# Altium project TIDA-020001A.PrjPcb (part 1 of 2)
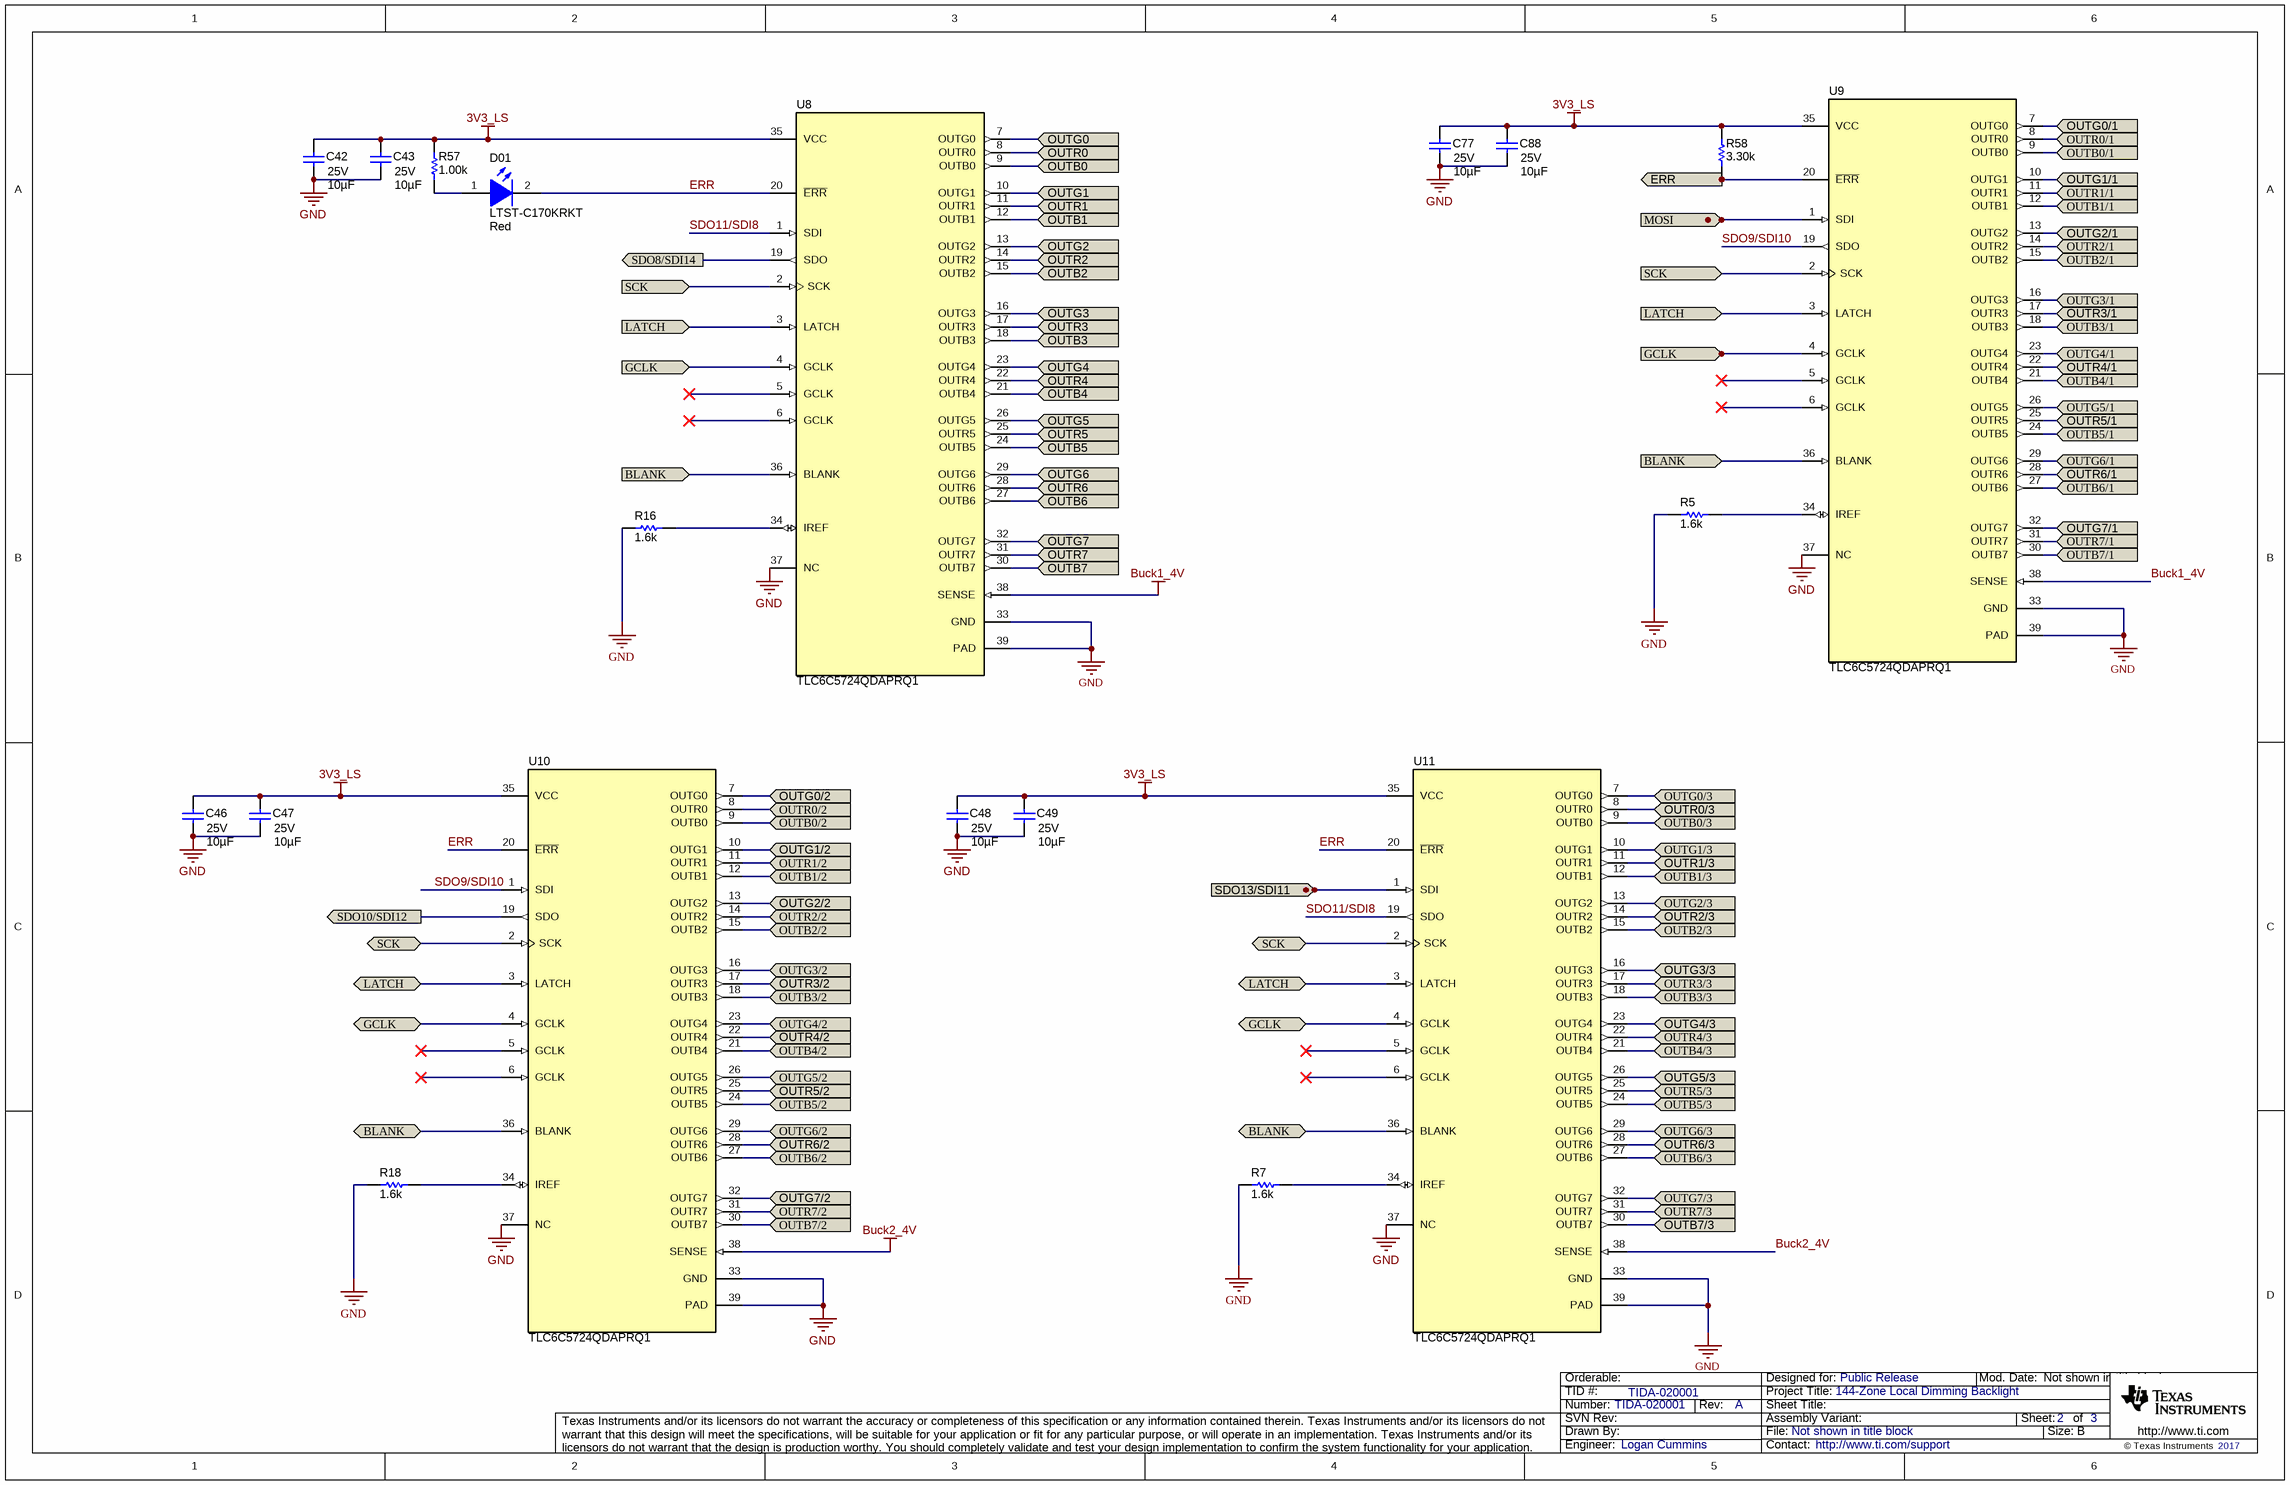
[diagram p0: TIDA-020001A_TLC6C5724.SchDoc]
TID: TIDA-020001; TechSupport: http://www.ti.com/support; SCH_Rev: A; PRJ_Title: 144-Zone Local Dimming Backlight; PRJ_Number: TIDA-020001; PRJ_Engineer: Logan Cummins; PRJ_Customer: Public Release; PCB_Rev: A; PCB_Layout: Logan Cummins; CopyrightYear: 2017
6 sheets, 284 parts. Net scope: global (net labels, ports and power ports of the same name join across sheets).
Board file: TIDA-020001A.PcbDoc
Sheets:
  TIDA-020001A_TLC6C5724.SchDoc
  TIDA-020001A_TLC6C5716.SchDoc
  TIDA-020001A_OPT&C2000.SchDoc
  TIDA-020001A_LEDs.SchDoc
  TIDA-020001A_LM74700&LMR14030.SchDoc
  TIDA-020001A_Hardware.SchDoc

## Sheet TIDA-020001A_TLC6C5724.SchDoc
size 431 x 279 mm; Date: Not shown in title block; ApprovedBy: Not shown in title block; CheckedBy: Not shown in title block; Author: Not shown in title block; CompanyName: Not shown in title block; Engineer: Not shown in title block; Organization: Not shown in title block; Address1: Not shown in title block; Address2: Not shown in title block; Address3: Not shown in title block; Address4: Not shown in title block; DocumentNumber: 1; Revision: Use project parameter SCH_Rev; SheetNumber: 2; SheetTotal: 3; PageSetup: Record=PageOptions¦CenterHorizontal=True¦CenterVertical=True¦PrintScale=1.00¦XCorrection=1.00¦YCorrection=1.00¦PrintKind=0¦BorderSize=5000000¦LeftOffset=0¦BottomOffset=0¦Orientation=2¦PaperLength=1000¦PaperWidth=1000¦Scale=100¦PaperSource=15¦PrintQuality=600¦MediaType=1¦DitherType=10¦PaperKind=Letter¦PrintScaleMode=1

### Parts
C42  ValueDisplayed: 10µF  Value2: 25V  [0603]  (hidden comment: GRM188R61E106MA73D)
C43  ValueDisplayed: 10µF  Value2: 25V  [0603]  (hidden comment: GRM188R61E106MA73D)
C46  ValueDisplayed: 10µF  Value2: 25V  [0603]  (hidden comment: GRM188R61E106MA73D)
C47  ValueDisplayed: 10µF  Value2: 25V  [0603]  (hidden comment: GRM188R61E106MA73D)
C48  ValueDisplayed: 10µF  Value2: 25V  [0603]  (hidden comment: GRM188R61E106MA73D)
C49  ValueDisplayed: 10µF  Value2: 25V  [0603]  (hidden comment: GRM188R61E106MA73D)
C77  ValueDisplayed: 10µF  Value2: 25V  [0603]  (hidden comment: GRM188R61E106MA73D)
C88  ValueDisplayed: 10µF  Value2: 25V  [0603]  (hidden comment: GRM188R61E106MA73D)
D01  LTST-C170KRKT  value Red  [LED_LTST-C170_Red]
R5  ValueDisplayed: 1.6k  [0603]  (hidden comment: CRCW06031K60JNEA)
R7  ValueDisplayed: 1.6k  [0603]  (hidden comment: CRCW06031K60JNEA)
R16  ValueDisplayed: 1.6k  [0603]  (hidden comment: CRCW06031K60JNEA)
R18  ValueDisplayed: 1.6k  [0603]  (hidden comment: CRCW06031K60JNEA)
R57  ValueDisplayed: 1.00k  [0603]  (hidden comment: RNCF0603TKY1K00)
R58  ValueDisplayed: 3.30k  [0603]  (hidden comment: RC0603FR-073K3L)
U8  TLC6C5724QDAPRQ1  [DAP0038E]
U9  TLC6C5724QDAPRQ1  [DAP0038E]
U10  TLC6C5724QDAPRQ1  [DAP0038E]
U11  TLC6C5724QDAPRQ1  [DAP0038E]

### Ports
BLANK, ERR, GCLK, LATCH, MOSI, OUTB0, OUTB0/1, OUTB0/2, OUTB0/3, OUTB1, OUTB1/1, OUTB1/2, OUTB1/3, OUTB2, OUTB2/1, OUTB2/2, OUTB2/3, OUTB3, OUTB3/1, OUTB3/2, OUTB3/3, OUTB4, OUTB4/1, OUTB4/2, OUTB4/3, OUTB5, OUTB5/1, OUTB5/2, OUTB5/3, OUTB6, OUTB6/1, OUTB6/2, OUTB6/3, OUTB7, OUTB7/1, OUTB7/2, OUTB7/3, OUTG0, OUTG0/1, OUTG0/2, OUTG0/3, OUTG1, OUTG1/1, OUTG1/2, OUTG1/3, OUTG2, OUTG2/1, OUTG2/2, OUTG2/3, OUTG3, OUTG3/1, OUTG3/2, OUTG3/3, OUTG4, OUTG4/1, OUTG4/2, OUTG4/3, OUTG5, OUTG5/1, OUTG5/2, OUTG5/3, OUTG6, OUTG6/1, OUTG6/2, OUTG6/3, OUTG7, OUTG7/1, OUTG7/2, OUTG7/3, OUTR0, OUTR0/1, OUTR0/2, OUTR0/3, OUTR1, OUTR1/1, OUTR1/2, OUTR1/3, OUTR2, OUTR2/1, OUTR2/2, OUTR2/3, OUTR3, OUTR3/1, OUTR3/2, OUTR3/3, OUTR4, OUTR4/1, OUTR4/2, OUTR4/3, OUTR5, OUTR5/1, OUTR5/2, OUTR5/3, OUTR6, OUTR6/1, OUTR6/2, OUTR6/3, OUTR7, OUTR7/1, OUTR7/2, OUTR7/3, SCK, SDO8/SDI14, SDO10/SDI12, SDO13/SDI11

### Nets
3V3_LS: C42.1 C43.1 C46.1 C47.1 C48.1 C49.1 C77.1 C88.1 R57.2 R58.2 U8.35(VCC) U9.35(VCC) U10.35(VCC) U11.35(VCC)
Buck1_4V: U8.38(SENSE) U9.38(SENSE)
Buck2_4V: U10.38(SENSE) U11.38(SENSE)
GND: C42.2 C43.2 C46.2 C47.2 C48.2 C49.2 C77.2 C88.2 R5.1 R7.1 R16.1 R18.1 U8.33(GND) U8.37(NC) U8.39(PAD) U9.33(GND) U9.37(NC) U9.39(PAD) U10.33(GND) U10.37(NC) U10.39(PAD) U11.33(GND) U11.37(NC) U11.39(PAD)
BLANK: U8.36(BLANK) U9.36(BLANK) U10.36(BLANK) U11.36(BLANK) ; port BLANK
ERR: D01.2(K) R58.1 U8.20(~{ERR}) U9.20(~{ERR}) U10.20(~{ERR}) U11.20(~{ERR}) ; port ERR
GCLK: U8.4(GCLK) U9.4(GCLK) U10.4(GCLK) U11.4(GCLK) ; port GCLK
LATCH: U8.3(LATCH) U9.3(LATCH) U10.3(LATCH) U11.3(LATCH) ; port LATCH
MOSI: U9.1(SDI) ; port MOSI
OUTB0: U8.9(OUTB0) ; port OUTB0
OUTB0/1: U9.9(OUTB0) ; port OUTB0/1
OUTB0/2: U10.9(OUTB0) ; port OUTB0/2
OUTB0/3: U11.9(OUTB0) ; port OUTB0/3
OUTB1: U8.12(OUTB1) ; port OUTB1
OUTB1/1: U9.12(OUTB1) ; port OUTB1/1
OUTB1/2: U10.12(OUTB1) ; port OUTB1/2
OUTB1/3: U11.12(OUTB1) ; port OUTB1/3
OUTB2: U8.15(OUTB2) ; port OUTB2
OUTB2/1: U9.15(OUTB2) ; port OUTB2/1
OUTB2/2: U10.15(OUTB2) ; port OUTB2/2
OUTB2/3: U11.15(OUTB2) ; port OUTB2/3
OUTB3: U8.18(OUTB3) ; port OUTB3
OUTB3/1: U9.18(OUTB3) ; port OUTB3/1
OUTB3/2: U10.18(OUTB3) ; port OUTB3/2
OUTB3/3: U11.18(OUTB3) ; port OUTB3/3
OUTB4: U8.21(OUTB4) ; port OUTB4
OUTB4/1: U9.21(OUTB4) ; port OUTB4/1
OUTB4/2: U10.21(OUTB4) ; port OUTB4/2
OUTB4/3: U11.21(OUTB4) ; port OUTB4/3
OUTB5: U8.24(OUTB5) ; port OUTB5
OUTB5/1: U9.24(OUTB5) ; port OUTB5/1
OUTB5/2: U10.24(OUTB5) ; port OUTB5/2
OUTB5/3: U11.24(OUTB5) ; port OUTB5/3
OUTB6: U8.27(OUTB6) ; port OUTB6
OUTB6/1: U9.27(OUTB6) ; port OUTB6/1
OUTB6/2: U10.27(OUTB6) ; port OUTB6/2
OUTB6/3: U11.27(OUTB6) ; port OUTB6/3
OUTB7: U8.30(OUTB7) ; port OUTB7
OUTB7/1: U9.30(OUTB7) ; port OUTB7/1
OUTB7/2: U10.30(OUTB7) ; port OUTB7/2
OUTB7/3: U11.30(OUTB7) ; port OUTB7/3
OUTG0: U8.7(OUTG0) ; port OUTG0
OUTG0/1: U9.7(OUTG0) ; port OUTG0/1
OUTG0/2: U10.7(OUTG0) ; port OUTG0/2
OUTG0/3: U11.7(OUTG0) ; port OUTG0/3
OUTG1: U8.10(OUTG1) ; port OUTG1
OUTG1/1: U9.10(OUTG1) ; port OUTG1/1
OUTG1/2: U10.10(OUTG1) ; port OUTG1/2
OUTG1/3: U11.10(OUTG1) ; port OUTG1/3
OUTG2: U8.13(OUTG2) ; port OUTG2
OUTG2/1: U9.13(OUTG2) ; port OUTG2/1
OUTG2/2: U10.13(OUTG2) ; port OUTG2/2
OUTG2/3: U11.13(OUTG2) ; port OUTG2/3
OUTG3: U8.16(OUTG3) ; port OUTG3
OUTG3/1: U9.16(OUTG3) ; port OUTG3/1
OUTG3/2: U10.16(OUTG3) ; port OUTG3/2
OUTG3/3: U11.16(OUTG3) ; port OUTG3/3
OUTG4: U8.23(OUTG4) ; port OUTG4
OUTG4/1: U9.23(OUTG4) ; port OUTG4/1
OUTG4/2: U10.23(OUTG4) ; port OUTG4/2
OUTG4/3: U11.23(OUTG4) ; port OUTG4/3
OUTG5: U8.26(OUTG5) ; port OUTG5
OUTG5/1: U9.26(OUTG5) ; port OUTG5/1
OUTG5/2: U10.26(OUTG5) ; port OUTG5/2
OUTG5/3: U11.26(OUTG5) ; port OUTG5/3
OUTG6: U8.29(OUTG6) ; port OUTG6
OUTG6/1: U9.29(OUTG6) ; port OUTG6/1
OUTG6/2: U10.29(OUTG6) ; port OUTG6/2
OUTG6/3: U11.29(OUTG6) ; port OUTG6/3
OUTG7: U8.32(OUTG7) ; port OUTG7
OUTG7/1: U9.32(OUTG7) ; port OUTG7/1
OUTG7/2: U10.32(OUTG7) ; port OUTG7/2
OUTG7/3: U11.32(OUTG7) ; port OUTG7/3
OUTR0: U8.8(OUTR0) ; port OUTR0
OUTR0/1: U9.8(OUTR0) ; port OUTR0/1
OUTR0/2: U10.8(OUTR0) ; port OUTR0/2
OUTR0/3: U11.8(OUTR0) ; port OUTR0/3
OUTR1: U8.11(OUTR1) ; port OUTR1
OUTR1/1: U9.11(OUTR1) ; port OUTR1/1
OUTR1/2: U10.11(OUTR1) ; port OUTR1/2
OUTR1/3: U11.11(OUTR1) ; port OUTR1/3
OUTR2: U8.14(OUTR2) ; port OUTR2
OUTR2/1: U9.14(OUTR2) ; port OUTR2/1
OUTR2/2: U10.14(OUTR2) ; port OUTR2/2
OUTR2/3: U11.14(OUTR2) ; port OUTR2/3
OUTR3: U8.17(OUTR3) ; port OUTR3
OUTR3/1: U9.17(OUTR3) ; port OUTR3/1
OUTR3/2: U10.17(OUTR3) ; port OUTR3/2
OUTR3/3: U11.17(OUTR3) ; port OUTR3/3
OUTR4: U8.22(OUTR4) ; port OUTR4
OUTR4/1: U9.22(OUTR4) ; port OUTR4/1
OUTR4/2: U10.22(OUTR4) ; port OUTR4/2
OUTR4/3: U11.22(OUTR4) ; port OUTR4/3
OUTR5: U8.25(OUTR5) ; port OUTR5
OUTR5/1: U9.25(OUTR5) ; port OUTR5/1
OUTR5/2: U10.25(OUTR5) ; port OUTR5/2
OUTR5/3: U11.25(OUTR5) ; port OUTR5/3
OUTR6: U8.28(OUTR6) ; port OUTR6
OUTR6/1: U9.28(OUTR6) ; port OUTR6/1
OUTR6/2: U10.28(OUTR6) ; port OUTR6/2
OUTR6/3: U11.28(OUTR6) ; port OUTR6/3
OUTR7: U8.31(OUTR7) ; port OUTR7
OUTR7/1: U9.31(OUTR7) ; port OUTR7/1
OUTR7/2: U10.31(OUTR7) ; port OUTR7/2
OUTR7/3: U11.31(OUTR7) ; port OUTR7/3
SCK: U8.2(SCK) U9.2(SCK) U10.2(SCK) U11.2(SCK) ; port SCK
SDO8/SDI14: U8.19(SDO) ; port SDO8/SDI14
SDO9/SDI10: U9.19(SDO) U10.1(SDI)
SDO10/SDI12: U10.19(SDO) ; port SDO10/SDI12
SDO11/SDI8: U8.1(SDI) U11.19(SDO)
SDO13/SDI11: U11.1(SDI) ; port SDO13/SDI11
NetD01_1: D01.1(A) R57.1
NetR5_2: R5.2 U9.34(IREF)
NetR7_2: R7.2 U11.34(IREF)
NetR16_2: R16.2 U8.34(IREF)
NetR18_2: R18.2 U10.34(IREF)

Not connected (* = marked no-connect by the designer): U8 5(GCLK)* 6(GCLK)*; U9 5(GCLK)* 6(GCLK)*; U10 5(GCLK)* 6(GCLK)*; U11 5(GCLK)* 6(GCLK)*

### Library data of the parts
C42 C43 C46-C49 C77 C88 = GRM188R61E106MA73D: CAP, CERM, 10 µF, 25 V, +/- 20%, X5R, 0603; Manufacturer: MuRata; Polarized: N; CompType: Capacitor; Value: 10uF; U/M: EA; Cap_F: 0.00001; Tolerance_%: 20; Value1: Unknown; VDC_V: 25; TaMin_C: -55; TaMax_C: 85; SizeArea_mm2: 1.28; SizeAreaWB_mm2: 4.68; SizeX_mm: 1.6; SizeY_mm: 0.8; SizeZ_mm: 1; AEC Category: Q200
D01 = CMP-0002829-2: LED, Red, SMD; Manufacturer: Lite-On; Io_A: 20mA; SizeAreaWB_mm2: 6.75; Value1: W; U/M: EA; SizeZ_mm: 1.2; SizeX_mm: 2; SizeY_mm: 1.25; Vf_V: 2V; SizeArea_mm2: 2.5; Type: AlInGaP
R5 R7 R16 R18 = CRCW06031K60JNEA: RES, 1.6 k, 5%, 0.1 W, 0603; Manufacturer: Vishay-Dale; CompType: Resistor; Value: 1.6k; Res_ohm: 1600; Value_Code: 1k60; Tolerance_%: 5; Power_W: 0.1; Value2: 0.1W; VDC_V: 75; TempCo: 200 ppm/C; SizeArea_mm2: 1.28; SizeX_mm: 1.6; SizeY_mm: 0.8; SizeZ_mm: 1; EIA_Code: E24; U/M: EA; AEC Category: Q200
R57 = RNCF0603TKY1K00: RES, 1.00 k, 0.01%, 0.063 W, 0603; Manufacturer: Stackpole Electronics Inc; CompType: Resistor; Value: 1.00k; Res_ohm: 1000; Value_Code: 1k00; Tolerance_%: 0.01; Power_W: 0.063; Value2: 0.063W; VDC_V: 50; TempCo: 5 ppm/C; SizeArea_mm2: 1.28; SizeX_mm: 1.6; SizeY_mm: 0.8; SizeZ_mm: 1; U/M: EA; AEC Category: Q200; Green_Lifecycle: Active; Green_REACh: Passed
R58 = RC0603FR-073K3L: RES, 3.30 k, 1%, 0.1 W, 0603; Manufacturer: Yageo America; CompType: Resistor; Value: 3.30k; Res_ohm: 3300; Value_Code: 3k30; Tolerance_%: 1; Power_W: 0.1; Value2: 0.1W; VDC_V: 150; TempCo: 200 ppm/C; SizeArea_mm2: 1.28; SizeX_mm: 1.6; SizeY_mm: 0.8; U/M: EA; AEC Category: Q200; Green_Lifecycle: Active; Green_REACh: Passed
U8-U11 = TLC6C5724QDAPRQ1: 24-Channel, Full Diagnostics, Constant-Current LED Driver with 7-Bit Dot Correction and 12-Bit PWM Dimming, DAP0038E (TSSOP-38); Manufacturer: Texas Instruments; SymbolCreator: Altium; SizeArea_mm2: 101.25; SizeAreaWB_mm2: 146.45; SizeX_mm: 8.1; SizeY_mm: 12.5; SizeZ_mm: 1.2; CompType: IC; U/M: EA

## Sheet TIDA-020001A_TLC6C5716.SchDoc
size 431 x 279 mm; Date: Not shown in title block; ApprovedBy: Not shown in title block; CheckedBy: Not shown in title block; Author: Not shown in title block; CompanyName: Not shown in title block; Engineer: Not shown in title block; Organization: Not shown in title block; Address1: Not shown in title block; Address2: Not shown in title block; Address3: Not shown in title block; Address4: Not shown in title block; DocumentNumber: 1; Revision: Use project parameter SCH_Rev; SheetNumber: 2; SheetTotal: 3; PageSetup: Record=PageOptions¦CenterHorizontal=True¦CenterVertical=True¦PrintScale=1.00¦XCorrection=1.00¦YCorrection=1.00¦PrintKind=0¦BorderSize=5000000¦LeftOffset=0¦BottomOffset=0¦Orientation=2¦PaperLength=1000¦PaperWidth=1000¦Scale=100¦PaperSource=15¦PrintQuality=600¦MediaType=1¦DitherType=10¦PaperKind=Letter¦PrintScaleMode=1
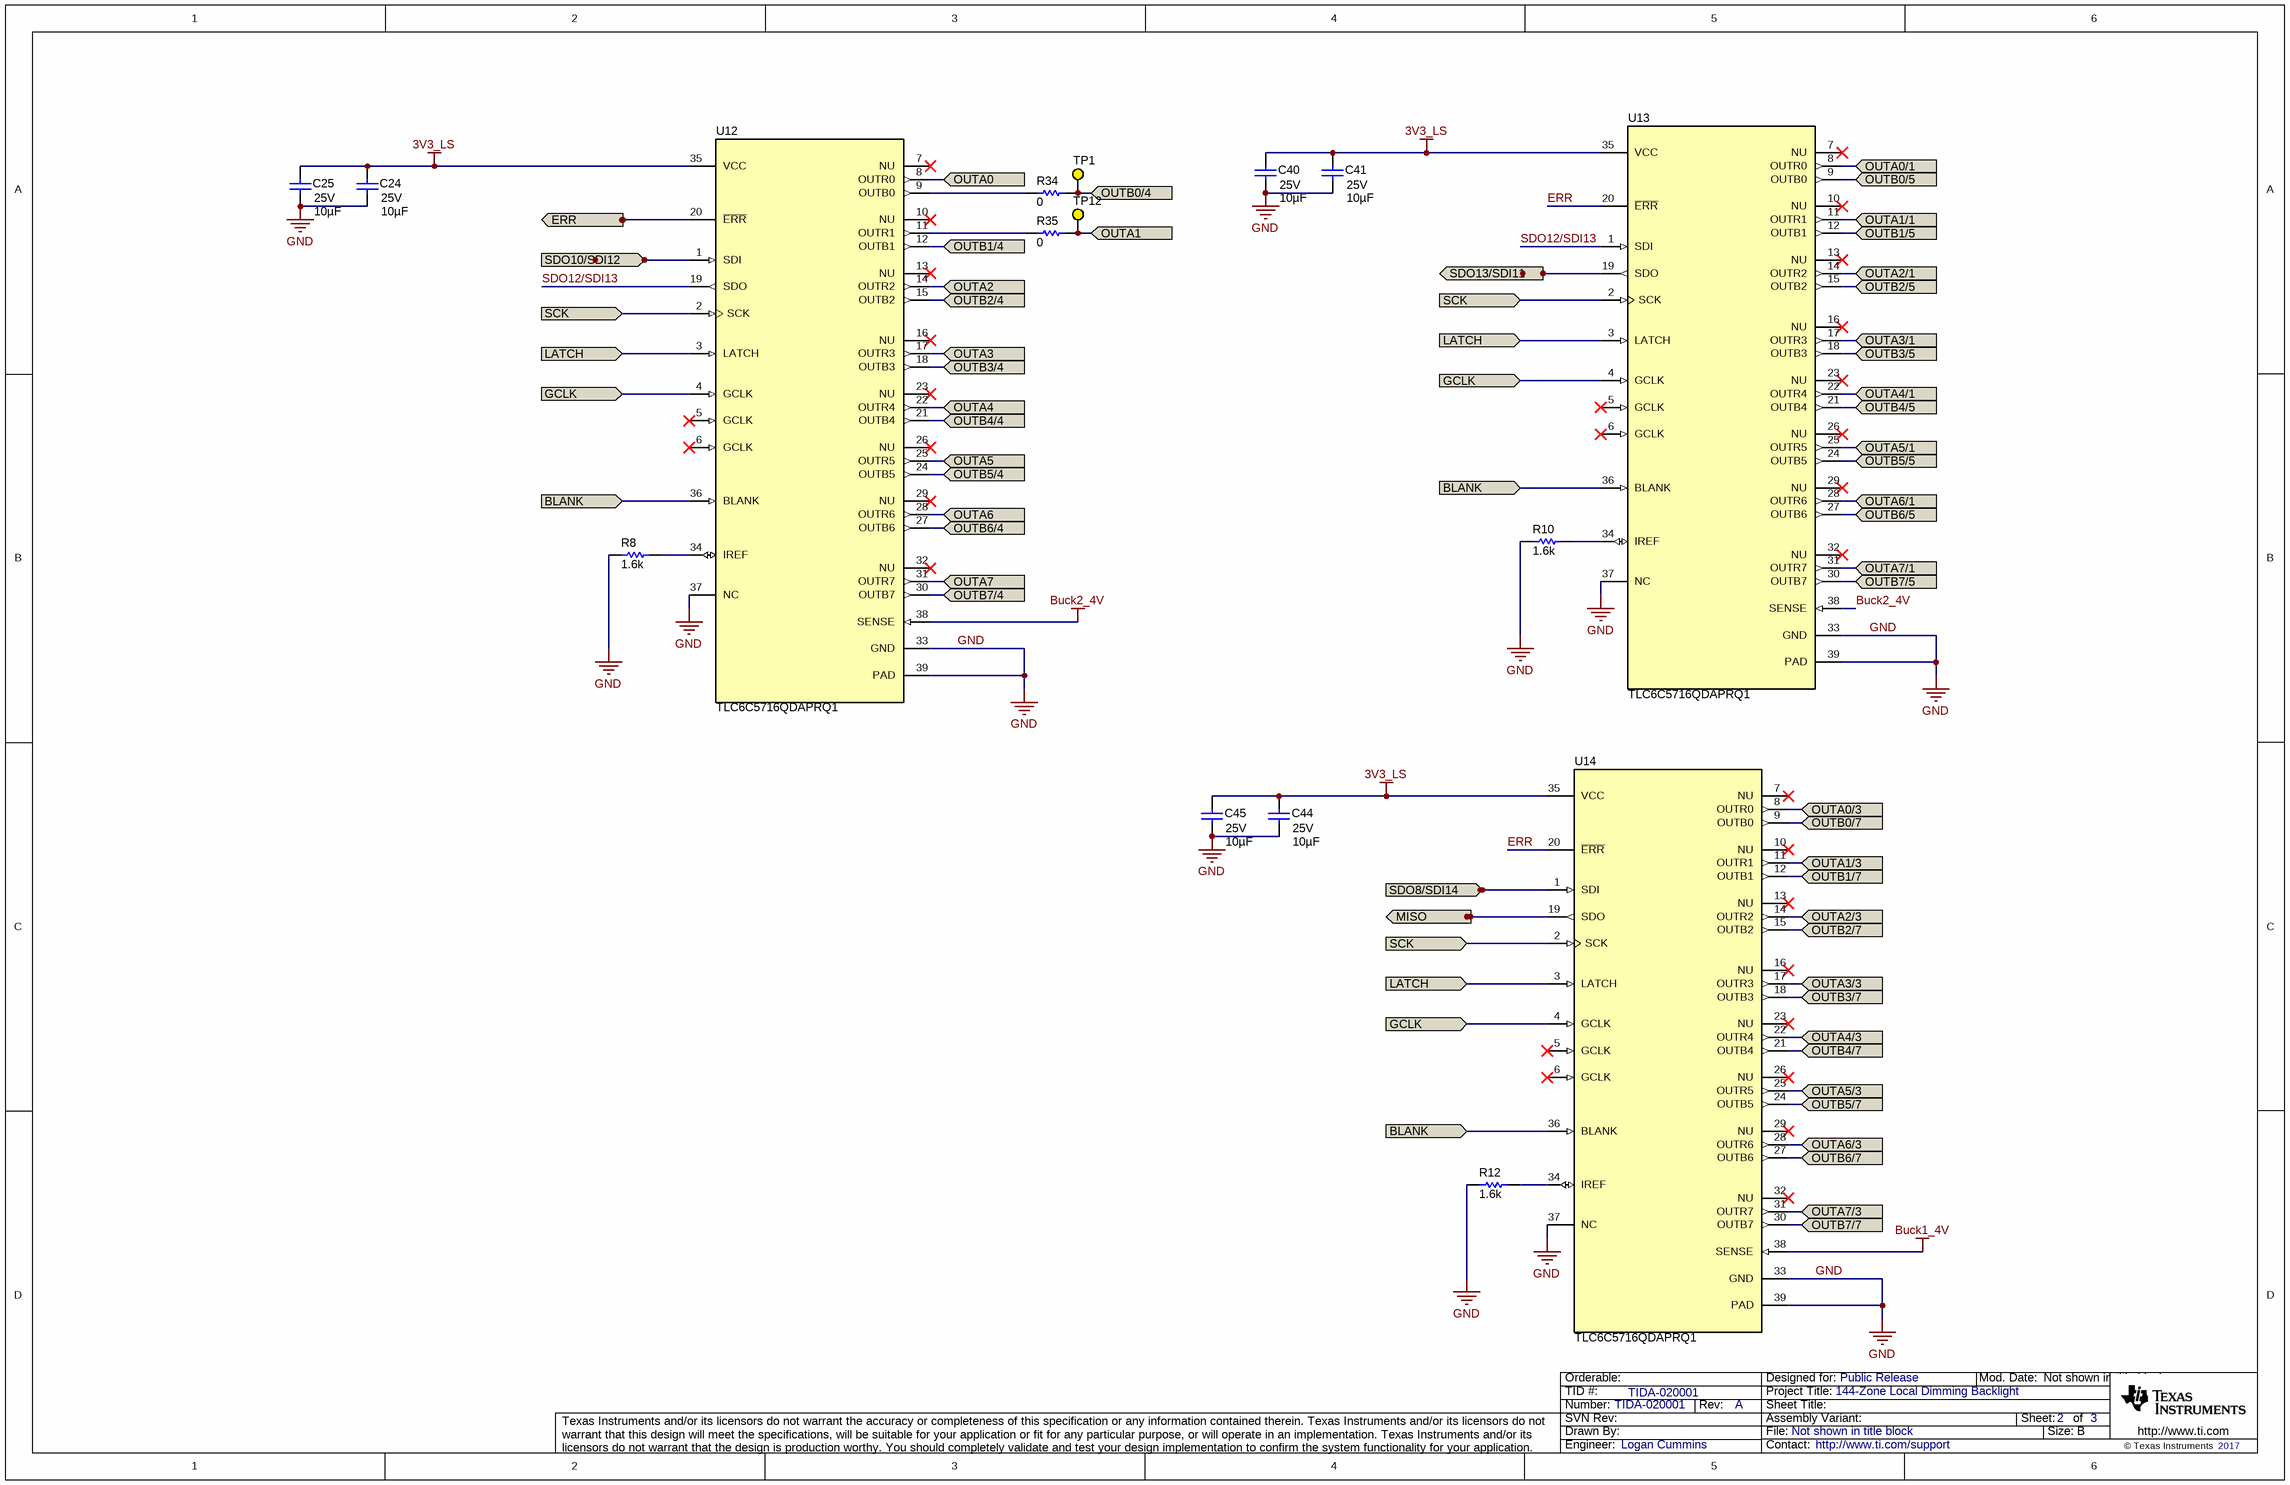
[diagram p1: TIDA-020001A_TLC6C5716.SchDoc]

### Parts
C24  ValueDisplayed: 10µF  Value2: 25V  [0603]  (hidden comment: GRM188R61E106MA73D)
C25  ValueDisplayed: 10µF  Value2: 25V  [0603]  (hidden comment: GRM188R61E106MA73D)
C40  ValueDisplayed: 10µF  Value2: 25V  [0603]  (hidden comment: GRM188R61E106MA73D)
C41  ValueDisplayed: 10µF  Value2: 25V  [0603]  (hidden comment: GRM188R61E106MA73D)
C44  ValueDisplayed: 10µF  Value2: 25V  [0603]  (hidden comment: GRM188R61E106MA73D)
C45  ValueDisplayed: 10µF  Value2: 25V  [0603]  (hidden comment: GRM188R61E106MA73D)
R8  ValueDisplayed: 1.6k  [0603]  (hidden comment: CRCW06031K60JNEA)
R10  ValueDisplayed: 1.6k  [0603]  (hidden comment: CRCW06031K60JNEA)
R12  ValueDisplayed: 1.6k  [0603]  (hidden comment: CRCW06031K60JNEA)
R34  ValueDisplayed: 0  [0603]  (hidden comment: CRCW06030000Z0EA)
R35  ValueDisplayed: 0  [0603]  (hidden comment: CRCW06030000Z0EA)
TP1  5000  [Keystone5004]  (value not drawn)
TP12  5000  [Keystone5004]  (value not drawn)
U12  TLC6C5716QDAPRQ1  [DAP0038E]
U13  TLC6C5716QDAPRQ1  [DAP0038E]
U14  TLC6C5716QDAPRQ1  [DAP0038E]

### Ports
BLANK, ERR, GCLK, LATCH, MISO, OUTA0, OUTA0/1, OUTA0/3, OUTA1, OUTA1/1, OUTA1/3, OUTA2, OUTA2/1, OUTA2/3, OUTA3, OUTA3/1, OUTA3/3, OUTA4, OUTA4/1, OUTA4/3, OUTA5, OUTA5/1, OUTA5/3, OUTA6, OUTA6/1, OUTA6/3, OUTA7, OUTA7/1, OUTA7/3, OUTB0/4, OUTB0/5, OUTB0/7, OUTB1/4, OUTB1/5, OUTB1/7, OUTB2/4, OUTB2/5, OUTB2/7, OUTB3/4, OUTB3/5, OUTB3/7, OUTB4/4, OUTB4/5, OUTB4/7, OUTB5/4, OUTB5/5, OUTB5/7, OUTB6/4, OUTB6/5, OUTB6/7, OUTB7/4, OUTB7/5, OUTB7/7, SCK, SDO8/SDI14, SDO10/SDI12, SDO13/SDI11

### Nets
3V3_LS: C24.1 C25.1 C40.1 C41.1 C44.1 C45.1 U12.35(VCC) U13.35(VCC) U14.35(VCC)
Buck1_4V: U14.38(SENSE)
Buck2_4V: U12.38(SENSE) U13.38(SENSE)
GND: C24.2 C25.2 C40.2 C41.2 C44.2 C45.2 R8.1 R10.1 R12.1 U12.33(GND) U12.37(NC) U12.39(PAD) U13.33(GND) U13.37(NC) U13.39(PAD) U14.33(GND) U14.37(NC) U14.39(PAD)
BLANK: U12.36(BLANK) U13.36(BLANK) U14.36(BLANK) ; port BLANK
ERR: U12.20(~{ERR}) U13.20(~{ERR}) U14.20(~{ERR}) ; port ERR
GCLK: U12.4(GCLK) U13.4(GCLK) U14.4(GCLK) ; port GCLK
LATCH: U12.3(LATCH) U13.3(LATCH) U14.3(LATCH) ; port LATCH
MISO: U14.19(SDO) ; port MISO
OUTA0: U12.8(OUTR0) ; port OUTA0
OUTA0/1: U13.8(OUTR0) ; port OUTA0/1
OUTA0/3: U14.8(OUTR0) ; port OUTA0/3
OUTA1: R35.2 TP12.1 ; port OUTA1
OUTA1/1: U13.11(OUTR1) ; port OUTA1/1
OUTA1/3: U14.11(OUTR1) ; port OUTA1/3
OUTA2: U12.14(OUTR2) ; port OUTA2
OUTA2/1: U13.14(OUTR2) ; port OUTA2/1
OUTA2/3: U14.14(OUTR2) ; port OUTA2/3
OUTA3: U12.17(OUTR3) ; port OUTA3
OUTA3/1: U13.17(OUTR3) ; port OUTA3/1
OUTA3/3: U14.17(OUTR3) ; port OUTA3/3
OUTA4: U12.22(OUTR4) ; port OUTA4
OUTA4/1: U13.22(OUTR4) ; port OUTA4/1
OUTA4/3: U14.22(OUTR4) ; port OUTA4/3
OUTA5: U12.25(OUTR5) ; port OUTA5
OUTA5/1: U13.25(OUTR5) ; port OUTA5/1
OUTA5/3: U14.25(OUTR5) ; port OUTA5/3
OUTA6: U12.28(OUTR6) ; port OUTA6
OUTA6/1: U13.28(OUTR6) ; port OUTA6/1
OUTA6/3: U14.28(OUTR6) ; port OUTA6/3
OUTA7: U12.31(OUTR7) ; port OUTA7
OUTA7/1: U13.31(OUTR7) ; port OUTA7/1
OUTA7/3: U14.31(OUTR7) ; port OUTA7/3
OUTB0/4: R34.2 TP1.1 ; port OUTB0/4
OUTB0/5: U13.9(OUTB0) ; port OUTB0/5
OUTB0/7: U14.9(OUTB0) ; port OUTB0/7
OUTB1/4: U12.12(OUTB1) ; port OUTB1/4
OUTB1/5: U13.12(OUTB1) ; port OUTB1/5
OUTB1/7: U14.12(OUTB1) ; port OUTB1/7
OUTB2/4: U12.15(OUTB2) ; port OUTB2/4
OUTB2/5: U13.15(OUTB2) ; port OUTB2/5
OUTB2/7: U14.15(OUTB2) ; port OUTB2/7
OUTB3/4: U12.18(OUTB3) ; port OUTB3/4
OUTB3/5: U13.18(OUTB3) ; port OUTB3/5
OUTB3/7: U14.18(OUTB3) ; port OUTB3/7
OUTB4/4: U12.21(OUTB4) ; port OUTB4/4
OUTB4/5: U13.21(OUTB4) ; port OUTB4/5
OUTB4/7: U14.21(OUTB4) ; port OUTB4/7
OUTB5/4: U12.24(OUTB5) ; port OUTB5/4
OUTB5/5: U13.24(OUTB5) ; port OUTB5/5
OUTB5/7: U14.24(OUTB5) ; port OUTB5/7
OUTB6/4: U12.27(OUTB6) ; port OUTB6/4
OUTB6/5: U13.27(OUTB6) ; port OUTB6/5
OUTB6/7: U14.27(OUTB6) ; port OUTB6/7
OUTB7/4: U12.30(OUTB7) ; port OUTB7/4
OUTB7/5: U13.30(OUTB7) ; port OUTB7/5
OUTB7/7: U14.30(OUTB7) ; port OUTB7/7
SCK: U12.2(SCK) U13.2(SCK) U14.2(SCK) ; port SCK
SDO8/SDI14: U14.1(SDI) ; port SDO8/SDI14
SDO10/SDI12: U12.1(SDI) ; port SDO10/SDI12
SDO12/SDI13: U12.19(SDO) U13.1(SDI)
SDO13/SDI11: U13.19(SDO) ; port SDO13/SDI11
NetR8_2: R8.2 U12.34(IREF)
NetR10_2: R10.2 U13.34(IREF)
NetR12_2: R12.2 U14.34(IREF)
NetR34_1: R34.1 U12.9(OUTB0)
NetR35_1: R35.1 U12.11(OUTR1)

Not connected (* = marked no-connect by the designer): U12 5(GCLK)* 6(GCLK)* 7(NU)* 10(NU)* 13(NU)* 16(NU)* 23(NU)* 26(NU)* 29(NU)* 32(NU)*; U13 5(GCLK)* 6(GCLK)* 7(NU)* 10(NU)* 13(NU)* 16(NU)* 23(NU)* 26(NU)* 29(NU)* 32(NU)*; U14 5(GCLK)* 6(GCLK)* 7(NU)* 10(NU)* 13(NU)* 16(NU)* 23(NU)* 26(NU)* 29(NU)* 32(NU)*

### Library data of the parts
C24 C25 C40 C41 C44 C45 = GRM188R61E106MA73D: as C42 on sheet TIDA-020001A_TLC6C5724
R8 R10 R12 = CRCW06031K60JNEA: as R5 on sheet TIDA-020001A_TLC6C5724
R34 R35 = CRCW06030000Z0EA: RES, 0, 5%, 0.1 W, 0603; Manufacturer: Vishay-Dale; CompType: Resistor; Value: 0; Value_Code: 0000; Tolerance_%: 5; Power_W: 0.1; Value2: 0.1W; VDC_V: 75; TempCo: 200 ppm/C; SizeArea_mm2: 1.28; SizeX_mm: 1.6; SizeY_mm: 0.8; SizeZ_mm: 1; EIA_Code: E24; U/M: EA; AEC Category: Q200
TP1 TP12 = CMP-0055141-1: Test Point, Miniature, Yellow, TH; Manufacturer: Keystone; CNHeader: FALSE; Green_Lifecycle: Active; Green_REACh: Passed; ContactFinish: Silver; CT: TRUE
U12-U14 = CMP-0078396-2: Automotive Grade 16-Channel, Full Diagnostics, Constant-Current LED Driver with 7-Bit Dot Correction and 12-Bit PWM Dimming, DAP0038E (TSSOP-38); Manufacturer: Texas Instruments; SizeZ_mm: 1.2; SizeX_mm: 8.1; SizeY_mm: 12.5; AEC Category: Q200; AEC Qualified: Y; SizeArea_mm2: 101.25; CompType: IC; SizeAreaWB_mm2: 146.45

## Sheet TIDA-020001A_OPT&C2000.SchDoc
size 431 x 279 mm; Date: Not shown in title block; ApprovedBy: Not shown in title block; CheckedBy: Not shown in title block; Author: Not shown in title block; CompanyName: Not shown in title block; Engineer: Not shown in title block; Organization: Not shown in title block; Address1: Not shown in title block; Address2: Not shown in title block; Address3: Not shown in title block; Address4: Not shown in title block; DocumentNumber: 1; Revision: Use project parameter SCH_Rev; SheetNumber: 2; SheetTotal: 3; PageSetup: Record=PageOptions¦CenterHorizontal=True¦CenterVertical=True¦PrintScale=1.00¦XCorrection=1.00¦YCorrection=1.00¦PrintKind=0¦BorderSize=5000000¦LeftOffset=0¦BottomOffset=0¦Orientation=2¦PaperLength=1000¦PaperWidth=1000¦Scale=100¦PaperSource=15¦PrintQuality=600¦MediaType=1¦DitherType=10¦PaperKind=Letter¦PrintScaleMode=1
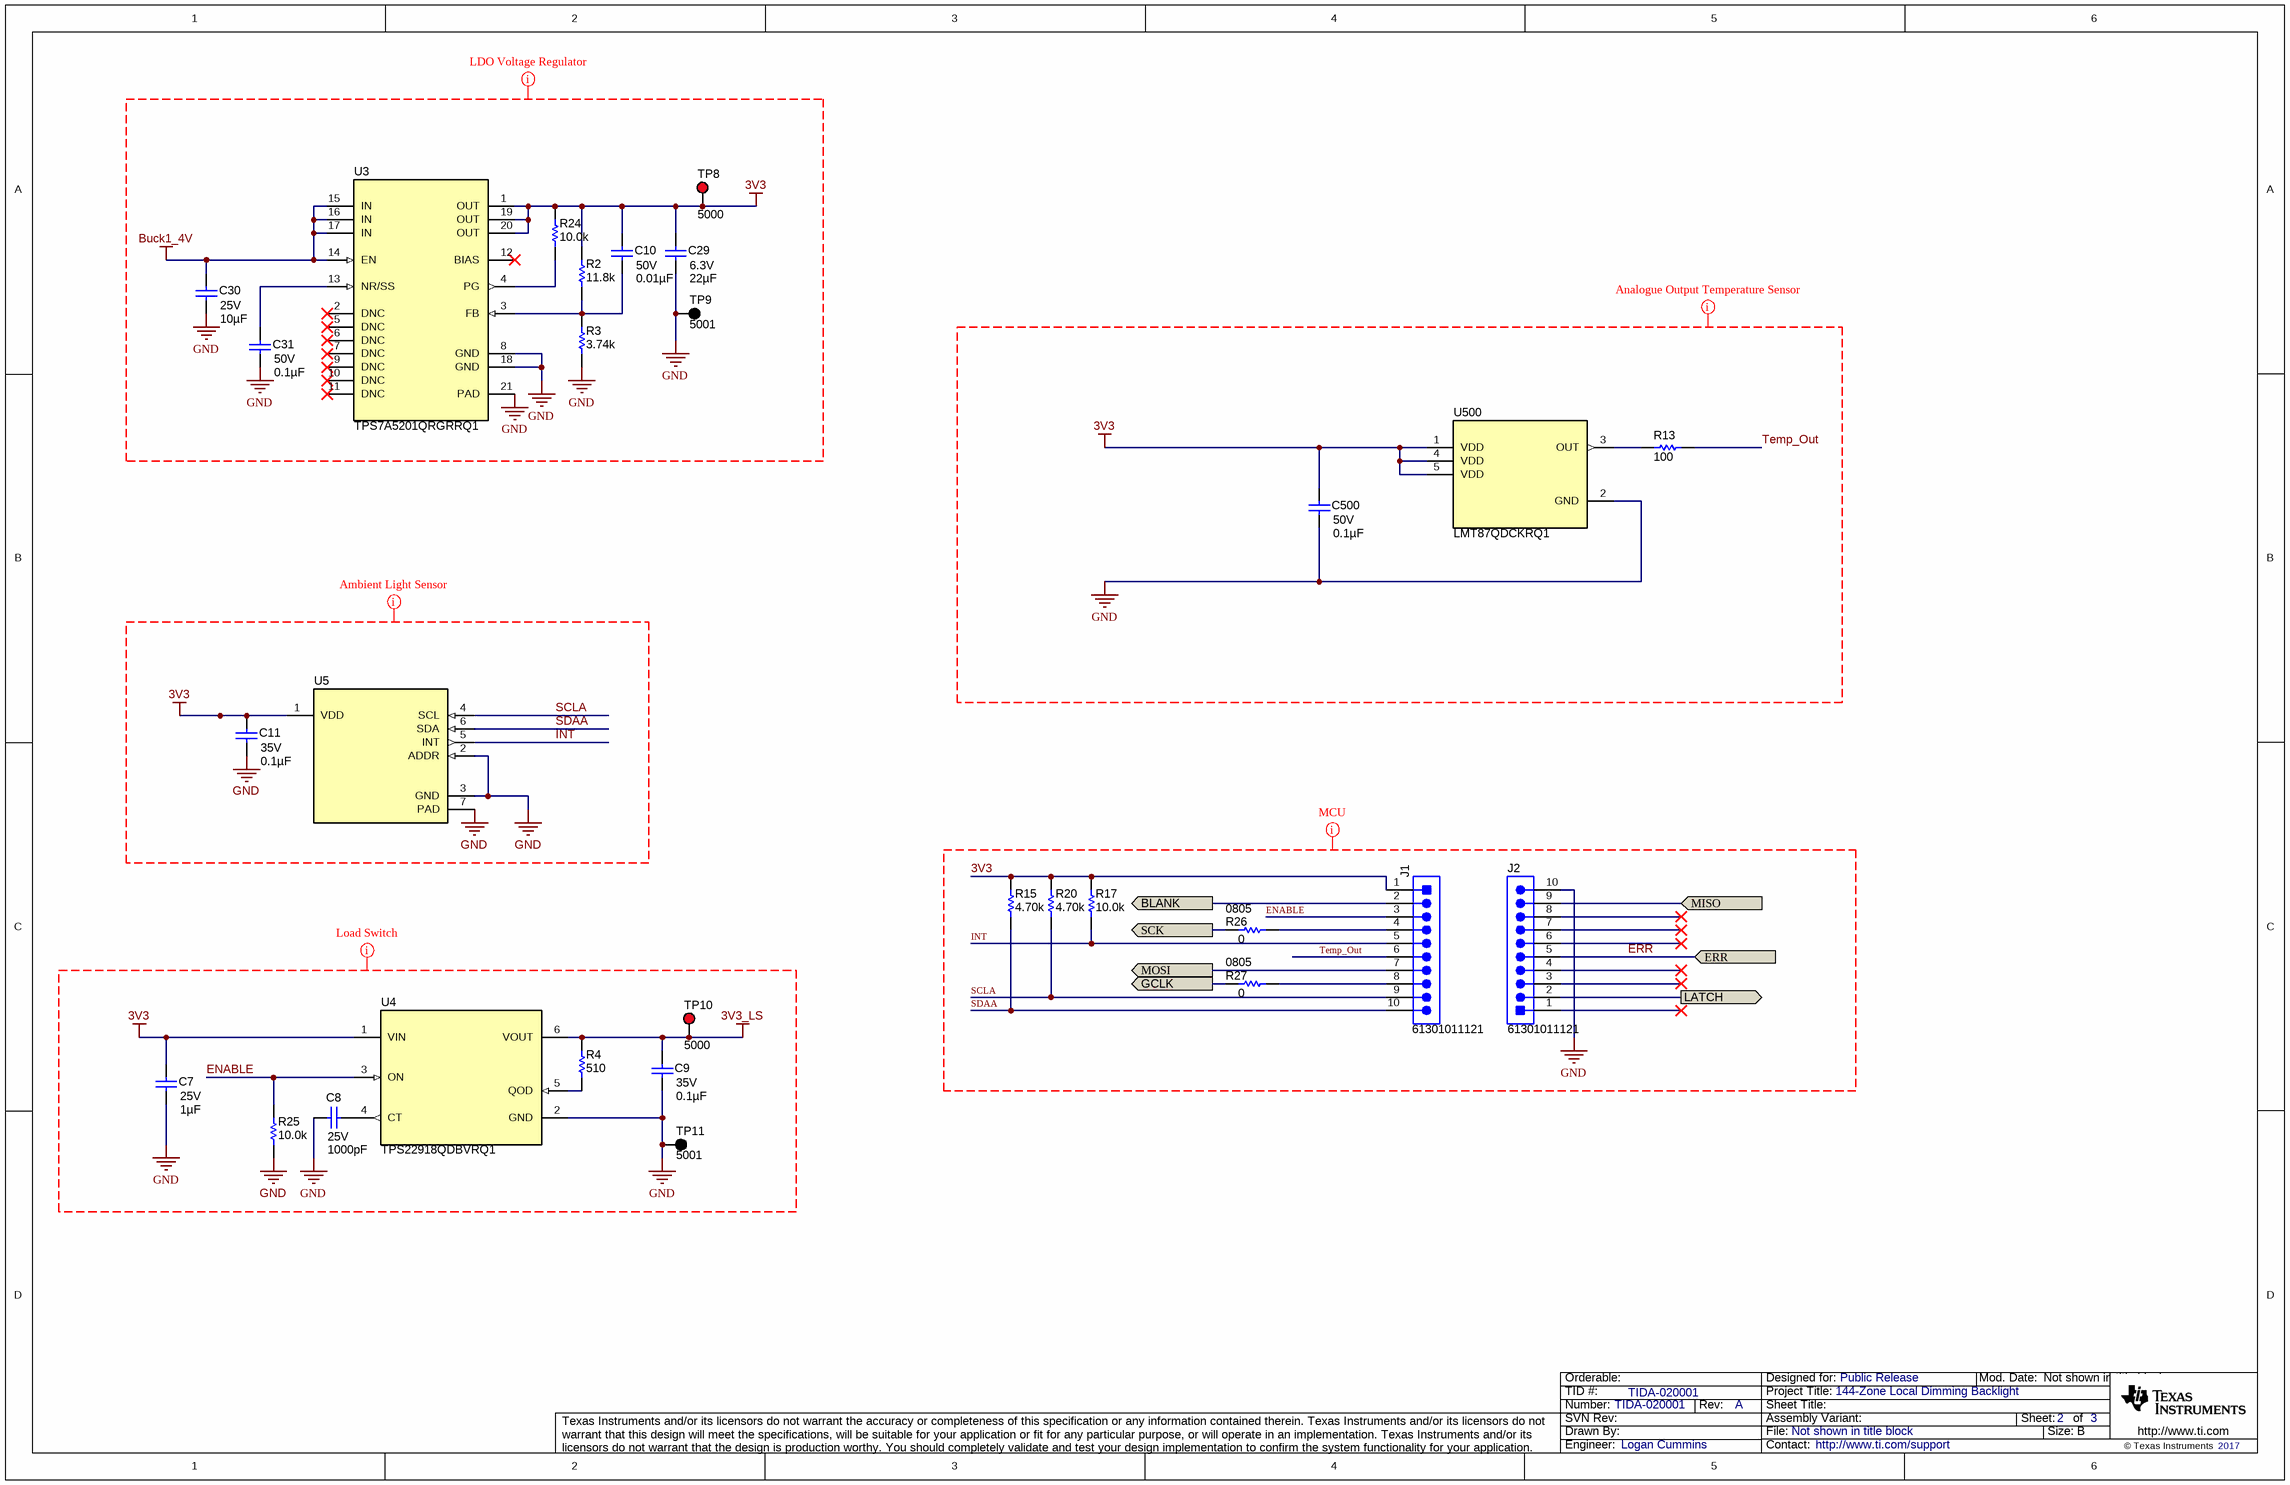
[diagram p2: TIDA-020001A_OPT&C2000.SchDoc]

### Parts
C7  ValueDisplayed: 1µF  Value2: 25V  [0402]  (hidden comment: C1005X5R1E105K050BC)
C8  ValueDisplayed: 1000pF  Value2: 25V  [0402]  (hidden comment: 885012205044)
C9  ValueDisplayed: 0.1µF  Value2: 35V  [0402]  (hidden comment: GMK105BJ104KV-F)
C10  ValueDisplayed: 0.01µF  Value2: 50V  [0805_HV]  (hidden comment: 08055C103JAT2A)
C11  ValueDisplayed: 0.1µF  Value2: 35V  [0402]  (hidden comment: GMK105BJ104KV-F)
C29  ValueDisplayed: 22µF  Value2: 6.3V  [0805_HV]  (hidden comment: JMK212BJ226KG-T)
C30  ValueDisplayed: 10µF  Value2: 25V  [0805_HV]  (hidden comment: GRM219R61E106KA12D)
C31  ValueDisplayed: 0.1µF  Value2: 50V  [0805_HV]  (hidden comment: C2012X5R1H104M085AA)
C500  ValueDisplayed: 0.1µF  Value2: 50V  [0603]  (hidden comment: GRM188R71H104KA93D)
J1  61301011121  [Wurth_61301011121]
J2  61301011121  [Wurth_61301011121]
R2  ValueDisplayed: 11.8k  [0603]  (hidden comment: CRCW060311K8FKEA)
R3  ValueDisplayed: 3.74k  [0603]  (hidden comment: RG1608P-3741-B-T5)
R4  ValueDisplayed: 510  [0603]  (hidden comment: RG1608P-511-B-T5)
R13  ValueDisplayed: 100  [0603]  (hidden comment: RC0603FR-07100RL)
R15  ValueDisplayed: 4.70k  [0603]  (hidden comment: RC0603FR-074K7L)
R17  ValueDisplayed: 10.0k  [0603]  (hidden comment: RMCF0603FT10K0)
R20  ValueDisplayed: 4.70k  [0603]  (hidden comment: RC0603FR-074K7L)
R24  ValueDisplayed: 10.0k  [0603]  (hidden comment: RMCF0603FT10K0)
R25  ValueDisplayed: 10.0k  [0603]  (hidden comment: RMCF0603FT10K0)
R26  PackageReference: 0805  ValueDisplayed: 0  [0805_HV]  (hidden comment: CRCW08050000Z0EA)
R27  PackageReference: 0805  ValueDisplayed: 0  [0805_HV]  (hidden comment: CRCW08050000Z0EA)
TP8  5000  [Keystone5000]
TP9  5001  [Keystone5001]
TP10  5000  [Keystone5000]
TP11  5001  [Keystone5001]
U3  TPS7A5201QRGRRQ1  [RGR0020A]
U4  TPS22918QDBVRQ1  [DBV0006A_N]
U5  OPT3001IDNPRQ1  [DNP0006A]  (value not drawn)
U500  LMT87QDCKRQ1  [DCK0005A_N]

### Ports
BLANK, ERR (in), GCLK, LATCH, MISO, MOSI, SCK

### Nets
3V3: C7.1 C10.1 C11.1 C29.1 C500.1 J1.1 R2.2 R15.2 R17.2 R20.2 R24.2 TP8.1 U3.1(OUT) U3.19(OUT) U3.20(OUT) U4.1(VIN) U5.1(VDD) U500.1(VDD) U500.4(VDD) U500.5(VDD)
3V3_LS: C9.1 R4.2 TP10.1 U4.6(VOUT)
Buck1_4V: C30.1 U3.14(EN) U3.15(IN) U3.16(IN) U3.17(IN)
GND: C7.2 C8.2 C9.2 C11.2 C29.2 C30.2 C31.2 C500.2 J2.10 R3.1 R25.1 TP9.1 TP11.1 U3.8(GND) U3.18(GND) U3.21(PAD) U4.2(GND) U5.2(ADDR) U5.3(GND) U5.7(PAD) U500.2(GND)
BLANK: J1.2 ; port BLANK
ENABLE: J1.3 R25.2 U4.3(ON)
ERR: J2.5 ; port ERR
GCLK: R27.1 ; port GCLK
INT: J1.5 R17.1 U5.5(INT)
LATCH: J2.2 ; port LATCH
MISO: J2.9 ; port MISO
MOSI: J1.7 ; port MOSI
SCK: R26.1 ; port SCK
SCLA: J1.9 R20.1 U5.4(SCL)
SDAA: J1.10 R15.1 U5.6(SDA)
Temp_Out: J1.6 R13.2
NetC8_1: C8.1 U4.4(CT)
NetC10_2: C10.2 R2.1 R3.2 U3.3(FB)
NetC31_1: C31.1 U3.13(NR/SS)
NetJ1_4: J1.4 R26.2
NetJ1_8: J1.8 R27.2
NetR4_1: R4.1 U4.5(QOD)
NetR13_1: R13.1 U500.3(OUT)
NetR24_1: R24.1 U3.4(PG)

Not connected (* = marked no-connect by the designer): J2 1* 3* 4* 6* 7* 8*; U3 2(DNC)* 5(DNC)* 6(DNC)* 7(DNC)* 9(DNC)* 10(DNC)* 11(DNC)* 12(BIAS)*

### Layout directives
net class Undefined: 3V3, 3V3_LS, Buck1_4V, ENABLE, ERR, GND, INT, SCLA, SDAA, Temp_Out
mark named Analogue Output Temperature Sensor: 3V3, GND, Temp_Out

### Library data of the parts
C7 = C1005X5R1E105K050BC: CAP, CERM, 1 µF, 25 V,+/- 10%, X5R, 0402; Manufacturer: TDK; Polarized: N; CompType: Capacitor; Value: 1uF; U/M: EA; Cap_F: 0.000001; Tolerance_%: 10; VDC_V: 25; TaMin_C: -55; TaMax_C: 80; SizeArea_mm2: 0.5; SizeAreaWB_mm2: 3; SizeX_mm: 1; SizeZ_mm: 0.6; AEC Category: Q200; Green_Lifecycle: Active; Green_REACh: Passed
C8 = 885012205044: CAP, CERM, 1000 pF, 25 V,+/- 10%, X7R, 0402; Manufacturer: Wurth Elektronik; Polarized: N; CompType: Capacitor; Value: 1000pF; U/M: EA; Cap_F: 0.000000001; Tolerance_%: 10; VDC_V: 25; TaMin_C: -55; TaMax_C: 125; SizeArea_mm2: 0.5; SizeAreaWB_mm2: 3; SizeX_mm: 1; SizeZ_mm: 0.6; AEC Category: Q200
C9 C11 = GMK105BJ104KV-F: CAP, CERM, 0.1 µF, 35 V,+/- 10%, X5R, 0402; Manufacturer: Taiyo Yuden; Polarized: N; CompType: Capacitor; Value: 0.1uF; U/M: EA; Cap_F: 0.0000001; Tolerance_%: 10; VDC_V: 35; TaMin_C: -55; TaMax_C: 85; SizeArea_mm2: 0.5; SizeAreaWB_mm2: 3; SizeX_mm: 1; SizeZ_mm: 0.6; AEC Category: Q200; Green_Lifecycle: Active; Green_REACh: Passed
C10 = 08055C103JAT2A: CAP, CERM, 0.01 µF, 50 V,+/- 5%, X7R, 0805; Manufacturer: AVX; Polarized: N; CompType: Capacitor; Value: 0.01uF; U/M: EA; Cap_F: 0.00000001; Tolerance_%: 5; ESR_ohm: 0.078; Value1: 0.078 ohm; VDC_V: 50; TaMin_C: -55; TaMax_C: 125; Cap_Case: 0805; SizeArea_mm2: 2.5; SizeAreaWB_mm2: 6.75; SizeX_mm: 2; SizeY_mm: 1.25; SizeZ_mm: 1.45; AEC Category: Q200; Green_Lifecycle: Active; Green_REACh: Passed
C29 = JMK212BJ226KG-T: CAP, CERM, 22 µF, 6.3 V,+/- 10%, X5R, 0805; Manufacturer: Taiyo Yuden; Polarized: N; CompType: Capacitor; Value: 22uF; U/M: EA; Cap_F: 0.000022; Tolerance_%: 10; ESR_ohm: 0.002; Value1: 0.002 ohm; VDC_V: 6.3; TaMin_C: -55; TaMax_C: 85; Cap_Case: 0805; SizeArea_mm2: 2.5; SizeAreaWB_mm2: 6.75; SizeX_mm: 2; SizeY_mm: 1.25; SizeZ_mm: 1.45; AEC Category: Q200; Green_Lifecycle: Not Set; Green_REACh: Incomplete
C30 = GRM219R61E106KA12D: CAP, CERM, 10 µF, 25 V,+/- 10%, X5R, 0805; Manufacturer: MuRata; Polarized: N; CompType: Capacitor; Value: 10uF; U/M: EA; Cap_F: 0.00001; Tolerance_%: 10; VDC_V: 25; TaMin_C: -55; TaMax_C: 85; Cap_Case: 0805; SizeArea_mm2: 2.5; SizeAreaWB_mm2: 6.75; SizeX_mm: 2; SizeY_mm: 1.25; SizeZ_mm: 1.45; AEC Category: Q200; Green_Lifecycle: Active; Green_REACh: Passed
C31 = C2012X5R1H104M085AA: CAP, CERM, 0.1 µF, 50 V,+/- 20%, X5R, 0805; Manufacturer: TDK; Polarized: N; CompType: Capacitor; Value: 0.1uF; U/M: EA; Cap_F: 0.0000001; Tolerance_%: 20; ESR_ohm: 0.02619; Value1: 0.02619 ohm; VDC_V: 50; IRMS_A: 1.29514; TaMin_C: -55; TaMax_C: 85; Cap_Case: 0805; SizeArea_mm2: 2.5; SizeAreaWB_mm2: 6.75; SizeX_mm: 2; SizeY_mm: 1.25; SizeZ_mm: 1.45; AEC Category: Q200; Green_Lifecycle: NRND; Green_REACh: Passed
C500 = GRM188R71H104KA93D: CAP, CERM, 0.1 µF, 50 V,+/- 10%, X7R, 0603; Manufacturer: MuRata; Polarized: N; CompType: Capacitor; Value: 0.1uF; U/M: EA; Cap_F: 0.0000001; Tolerance_%: 10; VDC_V: 50; TaMin_C: -55; TaMax_C: 125; SizeArea_mm2: 1.28; SizeAreaWB_mm2: 4.68; SizeX_mm: 1.6; SizeY_mm: 0.8; SizeZ_mm: 1; AEC Category: Q200; Green_Lifecycle: Active; Green_REACh: Passed
J1 J2 = CMP-0054804-1: Header, 2.54mm, 10x1, Gold, TH; Manufacturer: Wurth Elektronik; CNHeader: TRUE; Shrouded: N; Gender: Male; Row_Count: 1; Pitch_mm: 2.54; CT: FALSE
R2 = CRCW060311K8FKEA: RES, 11.8 k, 1%, 0.1 W, 0603; Manufacturer: Vishay-Dale; CompType: Resistor; Value: 11.8k; Res_ohm: 11800; Value_Code: 11k8; Tolerance_%: 1; Power_W: 0.1; Value2: 0.1W; VDC_V: 75; TempCo: 100 ppm/C; SizeArea_mm2: 1.28; SizeX_mm: 1.6; SizeY_mm: 0.8; EIA_Code: E96; U/M: EA; AEC Category: Q200; Green_Lifecycle: Active; Green_REACh: Passed
R3 = RG1608P-3741-B-T5: RES, 3.74 k, 0.1%, 0.1 W, 0603; Manufacturer: Susumu Co Ltd; CompType: Resistor; Value: 3.74k; Res_ohm: 3740; Value_Code: 3k74; Tolerance_%: 0.1; Value2: 0.1W; VDC_V: 75; TempCo: 25 ppm/C; SizeArea_mm2: 1.28; SizeX_mm: 1.6; SizeY_mm: 0.8; SizeZ_mm: 1; EIA_Code: E192; U/M: EA; AEC Category: Q200
R4 = RG1608P-511-B-T5: RES, 510, 0.1%, 0.1 W, 0603; Manufacturer: Susumu Co Ltd; CompType: Resistor; Value: 510; Value_Code: 510R; Tolerance_%: 0.1; Value2: 0.1W; VDC_V: 75; TempCo: 25 ppm/C; SizeArea_mm2: 1.28; SizeX_mm: 1.6; SizeY_mm: 0.8; SizeZ_mm: 1; U/M: EA; AEC Category: Q200
R13 = CMP-0022736-4: RES, 100, 1%, 0.1 W, 0603; Manufacturer: Yageo; Power_W: 100mW; TempCo: 100 ppm/C; Value_Code: 100R; Value: 100; EIA_Code: E96; SizeX_mm: 1.6; SizeY_mm: 0.8; SizeZ_mm: 1; Value2: 0.1W; SizeArea_mm2: 1.28; AEC Qualified: N; VDC_V: 75V; AEC Category: Q200; SizeAreaWB_mm2: 4.68
R15 R20 = RC0603FR-074K7L: RES, 4.70 k, 1%, 0.1 W, 0603; Manufacturer: Yageo America; CompType: Resistor; Value: 4.70k; Res_ohm: 4700; Value_Code: 4k70; Tolerance_%: 1; Power_W: 0.1; Value2: 0.1W; VDC_V: 150; TempCo: 200 ppm/C; SizeArea_mm2: 1.28; SizeX_mm: 1.6; SizeY_mm: 0.8; U/M: EA; AEC Category: Q200; Green_Lifecycle: Active; Green_REACh: Passed
R17 R24 R25 = RMCF0603FT10K0: RES, 10.0 k, 1%, 0.1 W, AEC-Q200 Grade 0, 0603; Manufacturer: Stackpole Electronics Inc; CompType: Resistor; Value: 10.0k; Res_ohm: 10000; Value_Code: 10k0; Tolerance_%: 1; Power_W: 0.1; Value2: 0.1W; VDC_V: 75; TempCo: 100 ppm/C; SizeArea_mm2: 1.28; SizeX_mm: 1.6; SizeY_mm: 0.8; EIA_Code: E96; U/M: EA; AEC Category: Q200; AEC Qualified: Y; AEC Grade: 0
R26 R27 = CMP-0020442-3: RES, 0, 5%, 0.125 W, AEC-Q200 Grade 0, 0805; Manufacturer: Vishay-Dale; Power_W: 125mW; TempCo: 200 ppm/C; Value_Code: 0000; Value: 0; EIA_Code: E24; SizeX_mm: 2; SizeY_mm: 1.25; SizeZ_mm: 1.45; Value2: 0.125W; SizeArea_mm2: 2.5; CompType: Resistor; AEC Qualified: Y; VDC_V: 150V; AEC Category: Q200
TP8 TP10 = CMP-0055137-1: Test Point, Miniature, Red, TH; Manufacturer: Keystone; CNHeader: FALSE; Green_Lifecycle: Active; Green_REACh: Passed; ContactFinish: Silver; CT: TRUE
TP9 TP11 = CMP-0055138-1: Test Point, Miniature, Black, TH; Manufacturer: Keystone; CNHeader: FALSE; Green_Lifecycle: Active; Green_REACh: Passed; ContactFinish: Silver; CT: TRUE
U3 = CMP-0077252-2: Automotive-Grade 2-A, High-Accuracy, Low-Noise, LDO Voltage Regulator, RGR0020A (VQFN-20); Alternate Manufacturer: Texas Instruments; AEC Qualified: Y; CompType: IC; SizeX_mm: 3.5; SizeAreaWB_mm2: 20.25; AEC Category: Q200; SizeZ_mm: 1.0; SizeArea_mm2: 12.25
U4 = TPS22918QDBVRQ1: 5.5-V, 2-A, 54mohm On-Resistance Load Switch, DBV0006A (SOT-23-6); Manufacturer: Texas Instruments; SymbolCreator: Altium; SizeArea_mm2: 8.12; SizeAreaWB_mm2: 14.82; SizeX_mm: 2.8; SizeY_mm: 2.9; SizeZ_mm: 1.45; CompType: IC; U/M: EA
U5 = CMP-0074867-2: Ambient Light Sensor (ALS), DNP0006A (USON-6); Alternate PartNumber: OPT3001IDNPTQ1; Alternate Manufacturer: Texas Instruments; SizeAreaWB_mm2: 9.0; U/M: EA; SizeZ_mm: 0.65; SizeX_mm: 2.0; SizeArea_mm2: 4.0; CompType: IC
U500 = CMP-0066236-2: Automotive Grade, 2.7V-Capable, 10 uA Analog Output Temperature Sensor, DCK0005A (SOT-SC70-5); Alternate PartNumber: LMT87QDCKTQ1; Alternate Manufacturer: Texas Instruments; SizeAreaWB_mm2: 9.3; SizeZ_mm: 1.1; SizeX_mm: 2.1; SizeY_mm: 2.0; SizeArea_mm2: 4.2; CompType: IC; AEC Category: Q200; AEC Qualified: Y

## Sheet TIDA-020001A_LEDs.SchDoc
size 571 x 381 mm; Date: Not shown in title block; ApprovedBy: Not shown in title block; CheckedBy: Not shown in title block; Author: Not shown in title block; CompanyName: Not shown in title block; Engineer: Not shown in title block; Organization: Not shown in title block; Address1: Not shown in title block; Address2: Not shown in title block; Address3: Not shown in title block; Address4: Not shown in title block; DocumentNumber: 1; Revision: Use project parameter SCH_Rev; SheetNumber: 2; SheetTotal: 3; PageSetup: Record=PageOptions¦CenterHorizontal=True¦CenterVertical=True¦PrintScale=1.00¦XCorrection=1.00¦YCorrection=1.00¦PrintKind=0¦BorderSize=5000000¦LeftOffset=0¦BottomOffset=0¦Orientation=2¦PaperLength=1000¦PaperWidth=1000¦Scale=100¦PaperSource=15¦PrintQuality=600¦MediaType=1¦DitherType=10¦PaperKind=Letter¦PrintScaleMode=1
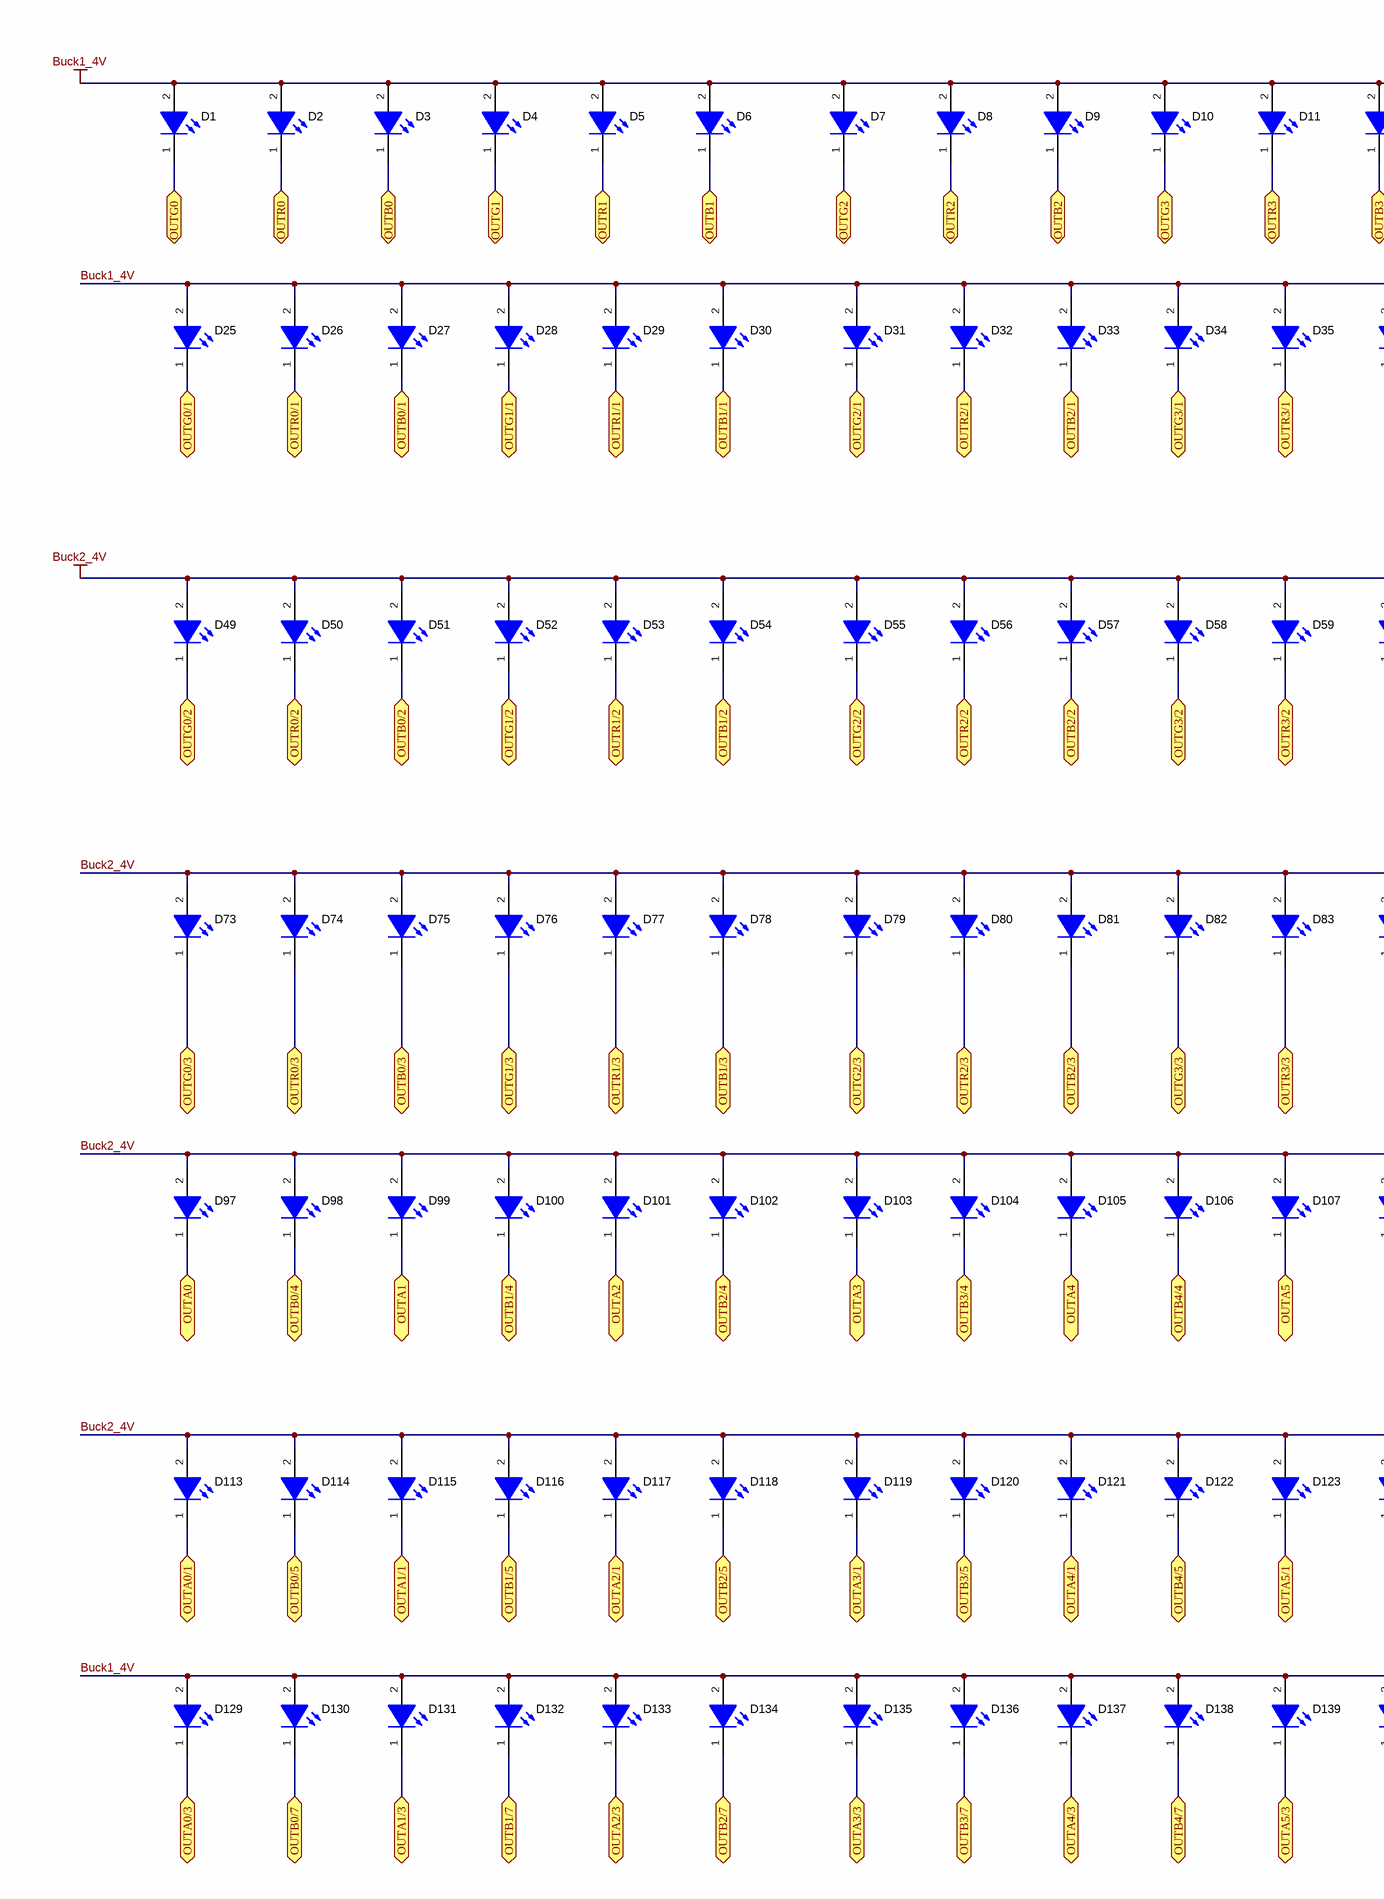
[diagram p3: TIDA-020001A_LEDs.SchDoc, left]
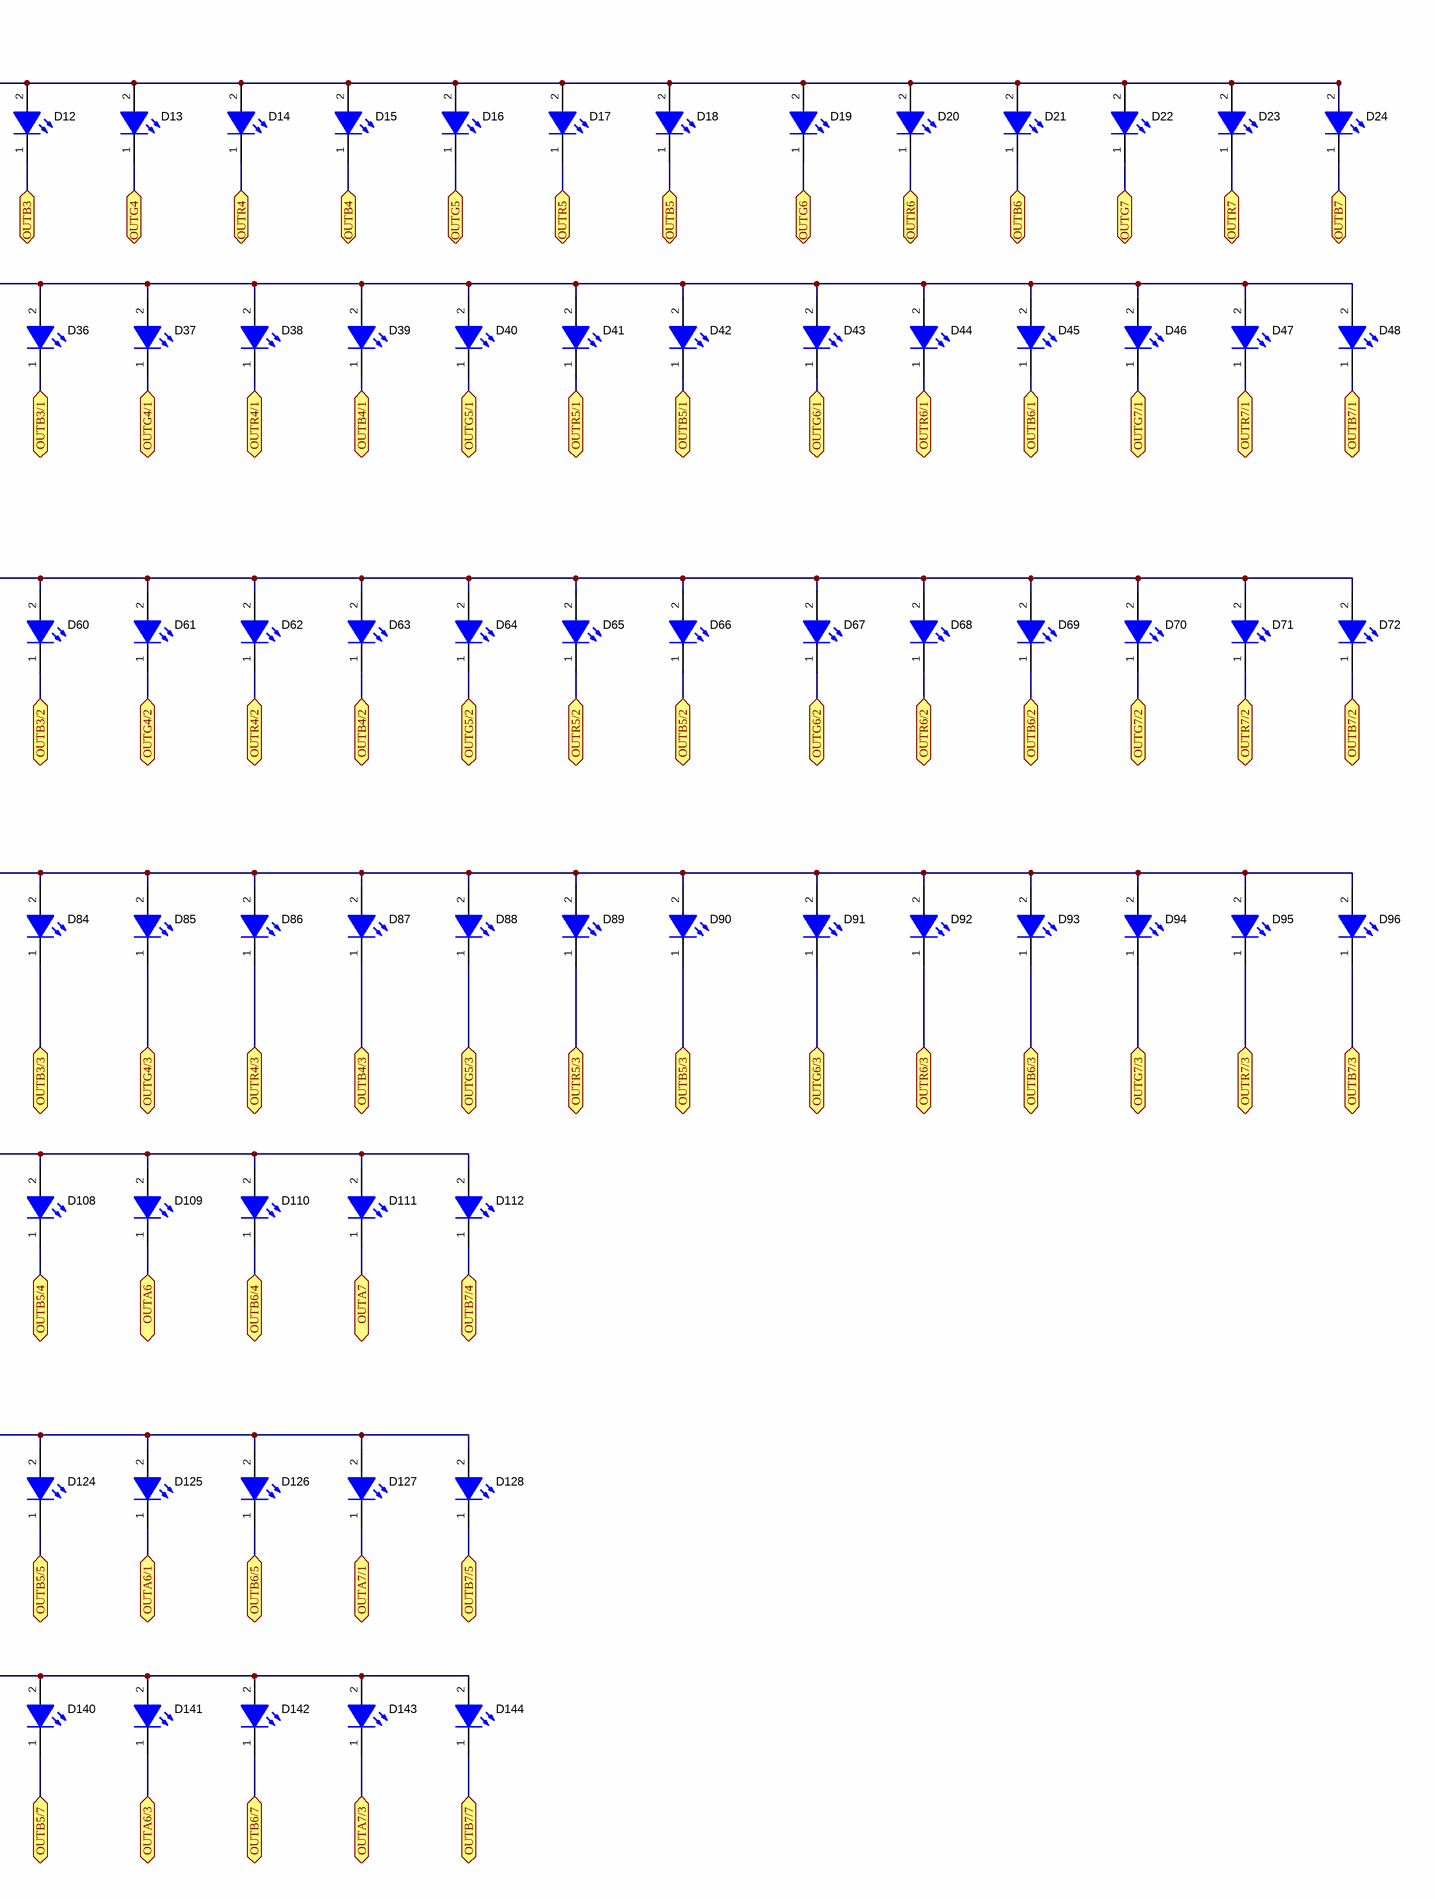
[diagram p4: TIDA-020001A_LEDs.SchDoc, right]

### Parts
D1  (no value)  [KW_DNLS31_RA_White]
D2  (no value)  [KW_DNLS31_RA_White]
D3  (no value)  [KW_DNLS31_RA_White]
D4  (no value)  [KW_DNLS31_RA_White]
D5  (no value)  [KW_DNLS31_RA_White]
D6  (no value)  [KW_DNLS31_RA_White]
D7  (no value)  [KW_DNLS31_RA_White]
D8  (no value)  [KW_DNLS31_RA_White]
D9  (no value)  [KW_DNLS31_RA_White]
D10  (no value)  [KW_DNLS31_RA_White]
D11  (no value)  [KW_DNLS31_RA_White]
D12  (no value)  [KW_DNLS31_RA_White]
D13  (no value)  [KW_DNLS31_RA_White]
D14  (no value)  [KW_DNLS31_RA_White]
D15  (no value)  [KW_DNLS31_RA_White]
D16  (no value)  [KW_DNLS31_RA_White]
D17  (no value)  [KW_DNLS31_RA_White]
D18  (no value)  [KW_DNLS31_RA_White]
D19  (no value)  [KW_DNLS31_RA_White]
D20  (no value)  [KW_DNLS31_RA_White]
D21  (no value)  [KW_DNLS31_RA_White]
D22  (no value)  [KW_DNLS31_RA_White]
D23  (no value)  [KW_DNLS31_RA_White]
D24  (no value)  [KW_DNLS31_RA_White]
D25  (no value)  [KW_DNLS31_RA_White]
D26  (no value)  [KW_DNLS31_RA_White]
D27  (no value)  [KW_DNLS31_RA_White]
D28  (no value)  [KW_DNLS31_RA_White]
D29  (no value)  [KW_DNLS31_RA_White]
D30  (no value)  [KW_DNLS31_RA_White]
D31  (no value)  [KW_DNLS31_RA_White]
D32  (no value)  [KW_DNLS31_RA_White]
D33  (no value)  [KW_DNLS31_RA_White]
D34  (no value)  [KW_DNLS31_RA_White]
D35  (no value)  [KW_DNLS31_RA_White]
D36  (no value)  [KW_DNLS31_RA_White]
D37  (no value)  [KW_DNLS31_RA_White]
D38  (no value)  [KW_DNLS31_RA_White]
D39  (no value)  [KW_DNLS31_RA_White]
D40  (no value)  [KW_DNLS31_RA_White]
D41  (no value)  [KW_DNLS31_RA_White]
D42  (no value)  [KW_DNLS31_RA_White]
D43  (no value)  [KW_DNLS31_RA_White]
D44  (no value)  [KW_DNLS31_RA_White]
D45  (no value)  [KW_DNLS31_RA_White]
D46  (no value)  [KW_DNLS31_RA_White]
D47  (no value)  [KW_DNLS31_RA_White]
D48  (no value)  [KW_DNLS31_RA_White]
D49  (no value)  [KW_DNLS31_RA_White]
D50  (no value)  [KW_DNLS31_RA_White]
D51  (no value)  [KW_DNLS31_RA_White]
D52  (no value)  [KW_DNLS31_RA_White]
D53  (no value)  [KW_DNLS31_RA_White]
D54  (no value)  [KW_DNLS31_RA_White]
D55  (no value)  [KW_DNLS31_RA_White]
D56  (no value)  [KW_DNLS31_RA_White]
D57  (no value)  [KW_DNLS31_RA_White]
D58  (no value)  [KW_DNLS31_RA_White]
D59  (no value)  [KW_DNLS31_RA_White]
D60  (no value)  [KW_DNLS31_RA_White]
D61  (no value)  [KW_DNLS31_RA_White]
D62  (no value)  [KW_DNLS31_RA_White]
D63  (no value)  [KW_DNLS31_RA_White]
D64  (no value)  [KW_DNLS31_RA_White]
D65  (no value)  [KW_DNLS31_RA_White]
D66  (no value)  [KW_DNLS31_RA_White]
D67  (no value)  [KW_DNLS31_RA_White]
D68  (no value)  [KW_DNLS31_RA_White]
D69  (no value)  [KW_DNLS31_RA_White]
D70  (no value)  [KW_DNLS31_RA_White]
D71  (no value)  [KW_DNLS31_RA_White]
D72  (no value)  [KW_DNLS31_RA_White]
D73  (no value)  [KW_DNLS31_RA_White]
D74  (no value)  [KW_DNLS31_RA_White]
D75  (no value)  [KW_DNLS31_RA_White]
D76  (no value)  [KW_DNLS31_RA_White]
D77  (no value)  [KW_DNLS31_RA_White]
D78  (no value)  [KW_DNLS31_RA_White]
D79  (no value)  [KW_DNLS31_RA_White]
D80  (no value)  [KW_DNLS31_RA_White]
D81  (no value)  [KW_DNLS31_RA_White]
D82  (no value)  [KW_DNLS31_RA_White]
D83  (no value)  [KW_DNLS31_RA_White]
D84  (no value)  [KW_DNLS31_RA_White]
D85  (no value)  [KW_DNLS31_RA_White]
D86  (no value)  [KW_DNLS31_RA_White]
D87  (no value)  [KW_DNLS31_RA_White]
D88  (no value)  [KW_DNLS31_RA_White]
D89  (no value)  [KW_DNLS31_RA_White]
D90  (no value)  [KW_DNLS31_RA_White]
D91  (no value)  [KW_DNLS31_RA_White]
D92  (no value)  [KW_DNLS31_RA_White]
D93  (no value)  [KW_DNLS31_RA_White]
D94  (no value)  [KW_DNLS31_RA_White]
D95  (no value)  [KW_DNLS31_RA_White]
D96  (no value)  [KW_DNLS31_RA_White]
D97  (no value)  [KW_DNLS31_RA_White]
D98  (no value)  [KW_DNLS31_RA_White]
D99  (no value)  [KW_DNLS31_RA_White]
D100  (no value)  [KW_DNLS31_RA_White]
D101  (no value)  [KW_DNLS31_RA_White]
D102  (no value)  [KW_DNLS31_RA_White]
D103  (no value)  [KW_DNLS31_RA_White]
D104  (no value)  [KW_DNLS31_RA_White]
D105  (no value)  [KW_DNLS31_RA_White]
D106  (no value)  [KW_DNLS31_RA_White]
D107  (no value)  [KW_DNLS31_RA_White]
D108  (no value)  [KW_DNLS31_RA_White]
D109  (no value)  [KW_DNLS31_RA_White]
D110  (no value)  [KW_DNLS31_RA_White]
D111  (no value)  [KW_DNLS31_RA_White]
D112  (no value)  [KW_DNLS31_RA_White]
D113  (no value)  [KW_DNLS31_RA_White]
D114  (no value)  [KW_DNLS31_RA_White]
D115  (no value)  [KW_DNLS31_RA_White]
D116  (no value)  [KW_DNLS31_RA_White]
D117  (no value)  [KW_DNLS31_RA_White]
D118  (no value)  [KW_DNLS31_RA_White]
D119  (no value)  [KW_DNLS31_RA_White]
D120  (no value)  [KW_DNLS31_RA_White]
D121  (no value)  [KW_DNLS31_RA_White]
D122  (no value)  [KW_DNLS31_RA_White]
D123  (no value)  [KW_DNLS31_RA_White]
D124  (no value)  [KW_DNLS31_RA_White]
D125  (no value)  [KW_DNLS31_RA_White]
D126  (no value)  [KW_DNLS31_RA_White]
D127  (no value)  [KW_DNLS31_RA_White]
D128  (no value)  [KW_DNLS31_RA_White]
D129  (no value)  [KW_DNLS31_RA_White]
D130  (no value)  [KW_DNLS31_RA_White]
D131  (no value)  [KW_DNLS31_RA_White]
D132  (no value)  [KW_DNLS31_RA_White]
D133  (no value)  [KW_DNLS31_RA_White]
D134  (no value)  [KW_DNLS31_RA_White]
D135  (no value)  [KW_DNLS31_RA_White]
D136  (no value)  [KW_DNLS31_RA_White]
D137  (no value)  [KW_DNLS31_RA_White]
D138  (no value)  [KW_DNLS31_RA_White]
D139  (no value)  [KW_DNLS31_RA_White]
D140  (no value)  [KW_DNLS31_RA_White]
D141  (no value)  [KW_DNLS31_RA_White]
D142  (no value)  [KW_DNLS31_RA_White]
D143  (no value)  [KW_DNLS31_RA_White]
D144  (no value)  [KW_DNLS31_RA_White]

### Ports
OUTA0, OUTA0/1, OUTA0/3, OUTA1, OUTA1/1, OUTA1/3, OUTA2, OUTA2/1, OUTA2/3, OUTA3, OUTA3/1, OUTA3/3, OUTA4, OUTA4/1, OUTA4/3, OUTA5, OUTA5/1, OUTA5/3, OUTA6, OUTA6/1, OUTA6/3, OUTA7, OUTA7/1, OUTA7/3, OUTB0, OUTB0/1, OUTB0/2, OUTB0/3, OUTB0/4, OUTB0/5, OUTB0/7, OUTB1, OUTB1/1, OUTB1/2, OUTB1/3, OUTB1/4, OUTB1/5, OUTB1/7, OUTB2, OUTB2/1, OUTB2/2, OUTB2/3, OUTB2/4, OUTB2/5, OUTB2/7, OUTB3, OUTB3/1, OUTB3/2, OUTB3/3, OUTB3/4, OUTB3/5, OUTB3/7, OUTB4, OUTB4/1, OUTB4/2, OUTB4/3, OUTB4/4, OUTB4/5, OUTB4/7, OUTB5, OUTB5/1, OUTB5/2, OUTB5/3, OUTB5/4, OUTB5/5, OUTB5/7, OUTB6, OUTB6/1, OUTB6/2, OUTB6/3, OUTB6/4, OUTB6/5, OUTB6/7, OUTB7, OUTB7/1, OUTB7/2, OUTB7/3, OUTB7/4, OUTB7/5, OUTB7/7, OUTG0, OUTG0/1, OUTG0/2, OUTG0/3, OUTG1, OUTG1/1, OUTG1/2, OUTG1/3, OUTG2, OUTG2/1, OUTG2/2, OUTG2/3, OUTG3, OUTG3/1, OUTG3/2, OUTG3/3, OUTG4, OUTG4/1, OUTG4/2, OUTG4/3, OUTG5, OUTG5/1, OUTG5/2, OUTG5/3, OUTG6, OUTG6/1, OUTG6/2, OUTG6/3, OUTG7, OUTG7/1, OUTG7/2, OUTG7/3, OUTR0, OUTR0/1, OUTR0/2, OUTR0/3, OUTR1, OUTR1/1, OUTR1/2, OUTR1/3, OUTR2, OUTR2/1, OUTR2/2, OUTR2/3, OUTR3, OUTR3/1, OUTR3/2, OUTR3/3, OUTR4, OUTR4/1, OUTR4/2, OUTR4/3, OUTR5, OUTR5/1, OUTR5/2, OUTR5/3, OUTR6, OUTR6/1, OUTR6/2, OUTR6/3, OUTR7, OUTR7/1, OUTR7/2, OUTR7/3

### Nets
Buck1_4V: D1.2(A) D2.2(A) D3.2(A) D4.2(A) D5.2(A) D6.2(A) D7.2(A) D8.2(A) D9.2(A) D10.2(A) D11.2(A) D12.2(A) D13.2(A) D14.2(A) D15.2(A) D16.2(A) D17.2(A) D18.2(A) D19.2(A) D20.2(A) D21.2(A) D22.2(A) D23.2(A) D24.2(A) D25.2(A) D26.2(A) D27.2(A) D28.2(A) D29.2(A) D30.2(A) D31.2(A) D32.2(A) D33.2(A) D34.2(A) D35.2(A) D36.2(A) D37.2(A) D38.2(A) D39.2(A) D40.2(A) D41.2(A) D42.2(A) D43.2(A) D44.2(A) D45.2(A) D46.2(A) D47.2(A) D48.2(A) D129.2(A) D130.2(A) D131.2(A) D132.2(A) D133.2(A) D134.2(A) D135.2(A) D136.2(A) D137.2(A) D138.2(A) D139.2(A) D140.2(A) D141.2(A) D142.2(A) D143.2(A) D144.2(A)
Buck2_4V: D49.2(A) D50.2(A) D51.2(A) D52.2(A) D53.2(A) D54.2(A) D55.2(A) D56.2(A) D57.2(A) D58.2(A) D59.2(A) D60.2(A) D61.2(A) D62.2(A) D63.2(A) D64.2(A) D65.2(A) D66.2(A) D67.2(A) D68.2(A) D69.2(A) D70.2(A) D71.2(A) D72.2(A) D73.2(A) D74.2(A) D75.2(A) D76.2(A) D77.2(A) D78.2(A) D79.2(A) D80.2(A) D81.2(A) D82.2(A) D83.2(A) D84.2(A) D85.2(A) D86.2(A) D87.2(A) D88.2(A) D89.2(A) D90.2(A) D91.2(A) D92.2(A) D93.2(A) D94.2(A) D95.2(A) D96.2(A) D97.2(A) D98.2(A) D99.2(A) D100.2(A) D101.2(A) D102.2(A) D103.2(A) D104.2(A) D105.2(A) D106.2(A) D107.2(A) D108.2(A) D109.2(A) D110.2(A) D111.2(A) D112.2(A) D113.2(A) D114.2(A) D115.2(A) D116.2(A) D117.2(A) D118.2(A) D119.2(A) D120.2(A) D121.2(A) D122.2(A) D123.2(A) D124.2(A) D125.2(A) D126.2(A) D127.2(A) D128.2(A)
OUTA0: D97.1(K) ; port OUTA0
OUTA0/1: D113.1(K) ; port OUTA0/1
OUTA0/3: D129.1(K) ; port OUTA0/3
OUTA1: D99.1(K) ; port OUTA1
OUTA1/1: D115.1(K) ; port OUTA1/1
OUTA1/3: D131.1(K) ; port OUTA1/3
OUTA2: D101.1(K) ; port OUTA2
OUTA2/1: D117.1(K) ; port OUTA2/1
OUTA2/3: D133.1(K) ; port OUTA2/3
OUTA3: D103.1(K) ; port OUTA3
OUTA3/1: D119.1(K) ; port OUTA3/1
OUTA3/3: D135.1(K) ; port OUTA3/3
OUTA4: D105.1(K) ; port OUTA4
OUTA4/1: D121.1(K) ; port OUTA4/1
OUTA4/3: D137.1(K) ; port OUTA4/3
OUTA5: D107.1(K) ; port OUTA5
OUTA5/1: D123.1(K) ; port OUTA5/1
OUTA5/3: D139.1(K) ; port OUTA5/3
OUTA6: D109.1(K) ; port OUTA6
OUTA6/1: D125.1(K) ; port OUTA6/1
OUTA6/3: D141.1(K) ; port OUTA6/3
OUTA7: D111.1(K) ; port OUTA7
OUTA7/1: D127.1(K) ; port OUTA7/1
OUTA7/3: D143.1(K) ; port OUTA7/3
OUTB0: D3.1(K) ; port OUTB0
OUTB0/1: D27.1(K) ; port OUTB0/1
OUTB0/2: D51.1(K) ; port OUTB0/2
OUTB0/3: D75.1(K) ; port OUTB0/3
OUTB0/4: D98.1(K) ; port OUTB0/4
OUTB0/5: D114.1(K) ; port OUTB0/5
OUTB0/7: D130.1(K) ; port OUTB0/7
OUTB1: D6.1(K) ; port OUTB1
OUTB1/1: D30.1(K) ; port OUTB1/1
OUTB1/2: D54.1(K) ; port OUTB1/2
OUTB1/3: D78.1(K) ; port OUTB1/3
OUTB1/4: D100.1(K) ; port OUTB1/4
OUTB1/5: D116.1(K) ; port OUTB1/5
OUTB1/7: D132.1(K) ; port OUTB1/7
OUTB2: D9.1(K) ; port OUTB2
OUTB2/1: D33.1(K) ; port OUTB2/1
OUTB2/2: D57.1(K) ; port OUTB2/2
OUTB2/3: D81.1(K) ; port OUTB2/3
OUTB2/4: D102.1(K) ; port OUTB2/4
OUTB2/5: D118.1(K) ; port OUTB2/5
OUTB2/7: D134.1(K) ; port OUTB2/7
OUTB3: D12.1(K) ; port OUTB3
OUTB3/1: D36.1(K) ; port OUTB3/1
OUTB3/2: D60.1(K) ; port OUTB3/2
OUTB3/3: D84.1(K) ; port OUTB3/3
OUTB3/4: D104.1(K) ; port OUTB3/4
OUTB3/5: D120.1(K) ; port OUTB3/5
OUTB3/7: D136.1(K) ; port OUTB3/7
OUTB4: D15.1(K) ; port OUTB4
OUTB4/1: D39.1(K) ; port OUTB4/1
OUTB4/2: D63.1(K) ; port OUTB4/2
OUTB4/3: D87.1(K) ; port OUTB4/3
OUTB4/4: D106.1(K) ; port OUTB4/4
OUTB4/5: D122.1(K) ; port OUTB4/5
OUTB4/7: D138.1(K) ; port OUTB4/7
OUTB5: D18.1(K) ; port OUTB5
OUTB5/1: D42.1(K) ; port OUTB5/1
OUTB5/2: D66.1(K) ; port OUTB5/2
OUTB5/3: D90.1(K) ; port OUTB5/3
OUTB5/4: D108.1(K) ; port OUTB5/4
OUTB5/5: D124.1(K) ; port OUTB5/5
OUTB5/7: D140.1(K) ; port OUTB5/7
OUTB6: D21.1(K) ; port OUTB6
OUTB6/1: D45.1(K) ; port OUTB6/1
OUTB6/2: D69.1(K) ; port OUTB6/2
OUTB6/3: D93.1(K) ; port OUTB6/3
OUTB6/4: D110.1(K) ; port OUTB6/4
OUTB6/5: D126.1(K) ; port OUTB6/5
OUTB6/7: D142.1(K) ; port OUTB6/7
OUTB7: D24.1(K) ; port OUTB7
OUTB7/1: D48.1(K) ; port OUTB7/1
OUTB7/2: D72.1(K) ; port OUTB7/2
OUTB7/3: D96.1(K) ; port OUTB7/3
OUTB7/4: D112.1(K) ; port OUTB7/4
OUTB7/5: D128.1(K) ; port OUTB7/5
OUTB7/7: D144.1(K) ; port OUTB7/7
OUTG0: D1.1(K) ; port OUTG0
OUTG0/1: D25.1(K) ; port OUTG0/1
OUTG0/2: D49.1(K) ; port OUTG0/2
OUTG0/3: D73.1(K) ; port OUTG0/3
OUTG1: D4.1(K) ; port OUTG1
OUTG1/1: D28.1(K) ; port OUTG1/1
OUTG1/2: D52.1(K) ; port OUTG1/2
OUTG1/3: D76.1(K) ; port OUTG1/3
OUTG2: D7.1(K) ; port OUTG2
OUTG2/1: D31.1(K) ; port OUTG2/1
OUTG2/2: D55.1(K) ; port OUTG2/2
OUTG2/3: D79.1(K) ; port OUTG2/3
OUTG3: D10.1(K) ; port OUTG3
OUTG3/1: D34.1(K) ; port OUTG3/1
OUTG3/2: D58.1(K) ; port OUTG3/2
OUTG3/3: D82.1(K) ; port OUTG3/3
OUTG4: D13.1(K) ; port OUTG4
OUTG4/1: D37.1(K) ; port OUTG4/1
OUTG4/2: D61.1(K) ; port OUTG4/2
OUTG4/3: D85.1(K) ; port OUTG4/3
OUTG5: D16.1(K) ; port OUTG5
OUTG5/1: D40.1(K) ; port OUTG5/1
OUTG5/2: D64.1(K) ; port OUTG5/2
OUTG5/3: D88.1(K) ; port OUTG5/3
OUTG6: D19.1(K) ; port OUTG6
OUTG6/1: D43.1(K) ; port OUTG6/1
OUTG6/2: D67.1(K) ; port OUTG6/2
OUTG6/3: D91.1(K) ; port OUTG6/3
OUTG7: D22.1(K) ; port OUTG7
OUTG7/1: D46.1(K) ; port OUTG7/1
OUTG7/2: D70.1(K) ; port OUTG7/2
OUTG7/3: D94.1(K) ; port OUTG7/3
OUTR0: D2.1(K) ; port OUTR0
OUTR0/1: D26.1(K) ; port OUTR0/1
OUTR0/2: D50.1(K) ; port OUTR0/2
OUTR0/3: D74.1(K) ; port OUTR0/3
OUTR1: D5.1(K) ; port OUTR1
OUTR1/1: D29.1(K) ; port OUTR1/1
OUTR1/2: D53.1(K) ; port OUTR1/2
OUTR1/3: D77.1(K) ; port OUTR1/3
OUTR2: D8.1(K) ; port OUTR2
OUTR2/1: D32.1(K) ; port OUTR2/1
OUTR2/2: D56.1(K) ; port OUTR2/2
OUTR2/3: D80.1(K) ; port OUTR2/3
OUTR3: D11.1(K) ; port OUTR3
OUTR3/1: D35.1(K) ; port OUTR3/1
OUTR3/2: D59.1(K) ; port OUTR3/2
OUTR3/3: D83.1(K) ; port OUTR3/3
OUTR4: D14.1(K) ; port OUTR4
OUTR4/1: D38.1(K) ; port OUTR4/1
OUTR4/2: D62.1(K) ; port OUTR4/2
OUTR4/3: D86.1(K) ; port OUTR4/3
OUTR5: D17.1(K) ; port OUTR5
OUTR5/1: D41.1(K) ; port OUTR5/1
OUTR5/2: D65.1(K) ; port OUTR5/2
OUTR5/3: D89.1(K) ; port OUTR5/3
OUTR6: D20.1(K) ; port OUTR6
OUTR6/1: D44.1(K) ; port OUTR6/1
OUTR6/2: D68.1(K) ; port OUTR6/2
OUTR6/3: D92.1(K) ; port OUTR6/3
OUTR7: D23.1(K) ; port OUTR7
OUTR7/1: D47.1(K) ; port OUTR7/1
OUTR7/2: D71.1(K) ; port OUTR7/2
OUTR7/3: D95.1(K) ; port OUTR7/3

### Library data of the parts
D1-D144 = CMP-0078618-1: LED, White, SMD; PartNumber: KW DNLS31.RA-6G7H-FK0PM0-22C2; Manufacturer: OSRAM; Tjmax_C: 125°C; SizeAreaWB_mm2: 7.92; Angle: 120; SizeArea_mm2: 3.22; SizeZ_mm: 0.75; Vf_V: 3.05V; SizeY_mm: 1.4; Value1: W; SizeX_mm: 2.3; Type: InGaN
